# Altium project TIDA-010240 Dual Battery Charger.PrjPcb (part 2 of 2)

## Sheet BQ25731_A.SchDoc
size 431 x 279 mm; Date: Not shown in title block; ApprovedBy: Not shown in title block; CheckedBy: Not shown in title block; Author: Not shown in title block; CompanyName: Not shown in title block; Engineer: Not shown in title block; Organization: Not shown in title block; Address1: Not shown in title block; Address2: Not shown in title block; Address3: Not shown in title block; Address4: Not shown in title block; DocumentNumber: 5; Revision: Use project parameter SCH_Rev; SheetNumber: 5; SheetTotal: 6; PageSetup: Record=PageOptions¦CenterHorizontal=True¦CenterVertical=True¦PrintScale=1.00¦XCorrection=1.00¦YCorrection=1.00¦PrintKind=0¦BorderSize=5000000¦LeftOffset=0¦BottomOffset=0¦Orientation=2¦PaperLength=1000¦PaperWidth=1000¦Scale=100¦PaperSource=15¦PrintQuality=600¦MediaType=1¦DitherType=10¦PaperKind=Letter¦PrintScaleMode=1
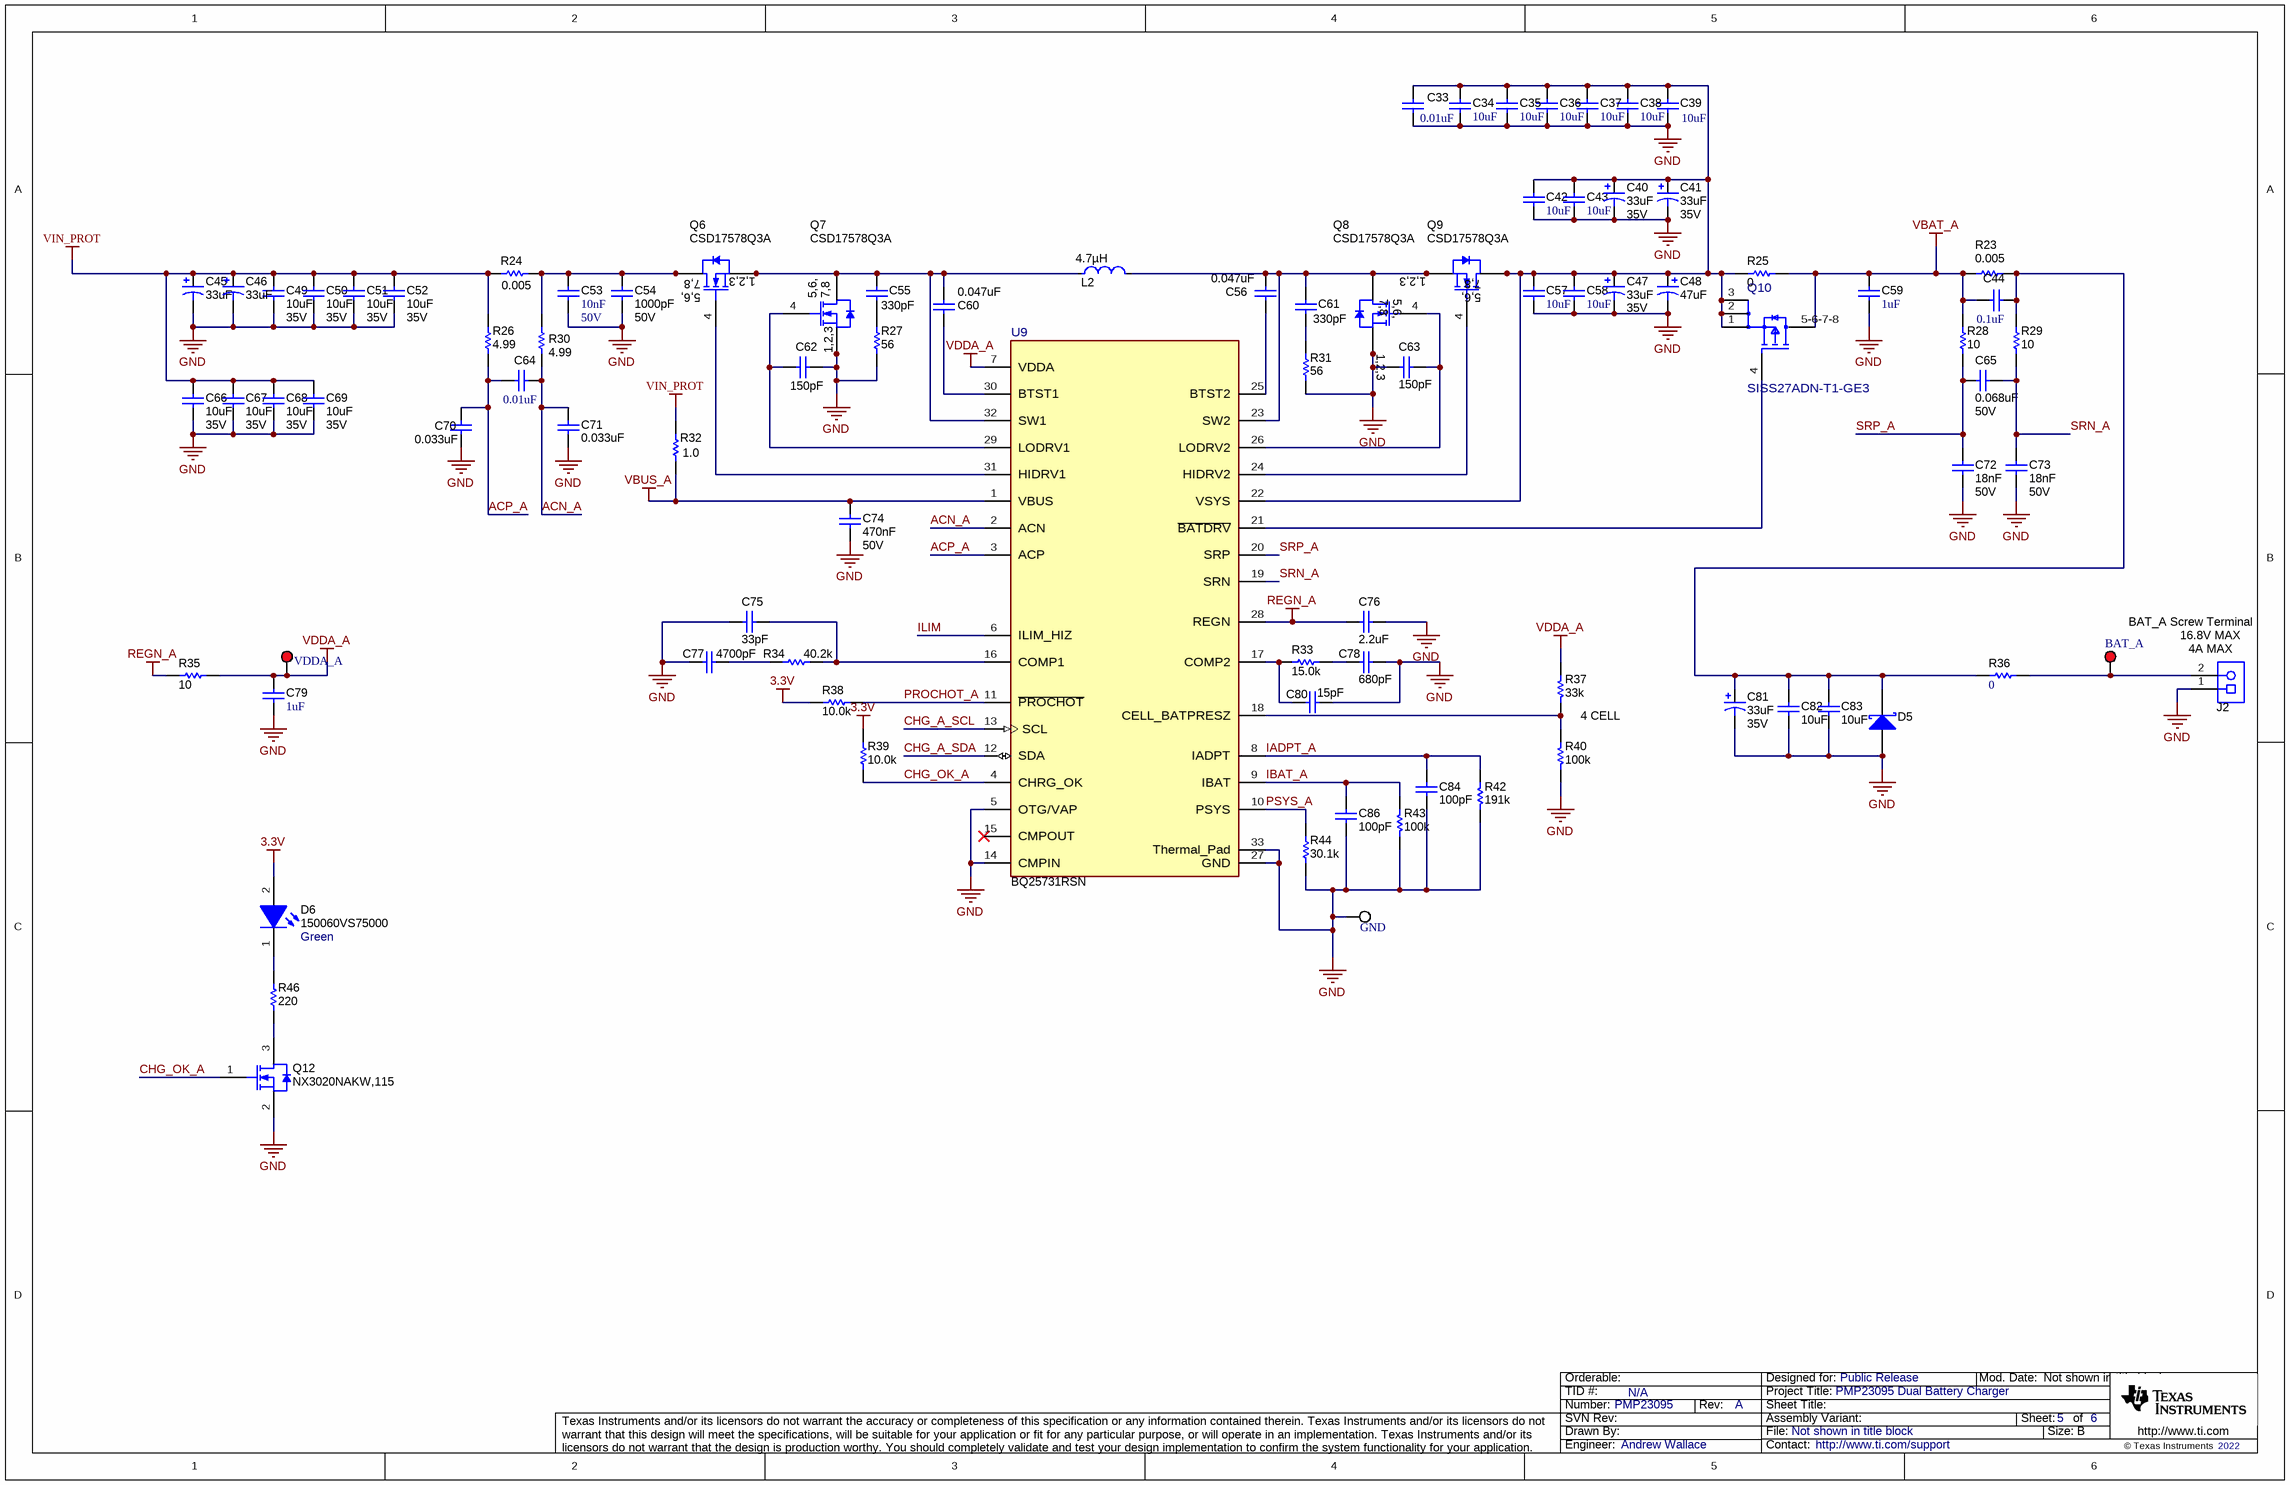
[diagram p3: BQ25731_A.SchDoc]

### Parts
BAT_A  5010  [Keystone5010]  (value not drawn)
C33  ValueDisplayed: 0.01uF  [0603L]  (hidden comment: C0603C103J5RACTU)
C34  ValueDisplayed: 10uF  [0805L]  (hidden comment: GRM21BR6YA106KE43L)
C35  ValueDisplayed: 10uF  [0805L]  (hidden comment: GRM21BR6YA106KE43L)
C36  ValueDisplayed: 10uF  [0805L]  (hidden comment: GRM21BR6YA106KE43L)
C37  ValueDisplayed: 10uF  [0805L]  (hidden comment: GRM21BR6YA106KE43L)
C38  ValueDisplayed: 10uF  [0805L]  (hidden comment: GRM21BR6YA106KE43L)
C39  ValueDisplayed: 10uF  [0805L]  (hidden comment: GRM21BR6YA106KE43L)
C40  ValueDisplayed: 33uF  VDC_V: 35V  [7343-31]  (hidden comment: T521D336M035ATE065)
C41  ValueDisplayed: 33uF  VDC_V: 35V  [7343-31]  (hidden comment: T521D336M035ATE065)
C42  ValueDisplayed: 10uF  [0805L]  (hidden comment: GRM21BR6YA106KE43L)
C43  ValueDisplayed: 10uF  [0805L]  (hidden comment: GRM21BR6YA106KE43L)
C44  ValueDisplayed: 0.1uF  [0603L]  (hidden comment: CGA3E2X7R1H104K080AA)
C45  ValueDisplayed: 33uF  [7343-31]  (hidden comment: T521D336M035ATE065)
C46  ValueDisplayed: 33uF  [7343-31]  (hidden comment: T521D336M035ATE065)
C47  ValueDisplayed: 33uF  VDC_V: 35V  [7343-31]  (hidden comment: T521D336M035ATE065)
C48  ValueDisplayed: 47uF  [CAPSMT_62_F61]  (hidden comment: Cap_Polarized)
C49  ValueDisplayed: 10uF  VDC_V: 35V  [0805L]  (hidden comment: GRM21BR6YA106KE43L)
C50  ValueDisplayed: 10uF  VDC_V: 35V  [0805L]  (hidden comment: GRM21BR6YA106KE43L)
C51  ValueDisplayed: 10uF  VDC_V: 35V  [0805L]  (hidden comment: GRM21BR6YA106KE43L)
C52  ValueDisplayed: 10uF  VDC_V: 35V  [0805L]  (hidden comment: GRM21BR6YA106KE43L)
C53  Cap_F: 10nF  VDC_V: 50V  [0603L]  (hidden comment: C0603C103J5RACTU)
C54  ValueDisplayed: 1000pF  VDC_V: 50V  [0402L]  (hidden comment: C1005NP01H102J050BA)
C55  ValueDisplayed: 330pF  [0603L]  (hidden comment: Capacitor)
C56  ValueDisplayed: 0.047uF  [0603L]  (hidden comment: Capacitor)
C57  ValueDisplayed: 10uF  [0805L]  (hidden comment: GRM21BR6YA106KE43L)
C58  ValueDisplayed: 10uF  [0805L]  (hidden comment: GRM21BR6YA106KE43L)
C59  ValueDisplayed: 1uF  [0603L]  (hidden comment: CGA3E1X7R1V105K080AC)
C60  ValueDisplayed: 0.047uF  [0603L]  (hidden comment: Capacitor)
C61  ValueDisplayed: 330pF  [0603L]  (hidden comment: Capacitor)
C62  ValueDisplayed: 150pF  [0603L]  (hidden comment: Capacitor)
C63  ValueDisplayed: 150pF  [0603L]  (hidden comment: Capacitor)
C64  ValueDisplayed: 0.01uF  [0603L]  (hidden comment: C0603C103J5RACTU)
C65  ValueDisplayed: 0.068uF  VDC_V: 50V  [0402L]  (hidden comment: CGA2B3X7R1H683K050BB)
C66  ValueDisplayed: 10uF  VDC_V: 35V  [0805L]  (hidden comment: GRM21BR6YA106KE43L)
C67  ValueDisplayed: 10uF  VDC_V: 35V  [0805L]  (hidden comment: GRM21BR6YA106KE43L)
C68  ValueDisplayed: 10uF  VDC_V: 35V  [0805L]  (hidden comment: GRM21BR6YA106KE43L)
C69  ValueDisplayed: 10uF  VDC_V: 35V  [0805L]  (hidden comment: GRM21BR6YA106KE43L)
C70  ValueDisplayed: 0.033uF  [0603L]  (hidden comment: GRM188R71H333KA61D)
C71  ValueDisplayed: 0.033uF  [0603L]  (hidden comment: GRM188R71H333KA61D)
C72  Cap_F: 18nF  VDC_V: 50V  [0603L]  (hidden comment: GRM188R71H183KA01D)
C73  Cap_F: 18nF  VDC_V: 50V  [0603L]  (hidden comment: GRM188R71H183KA01D)
C74  Cap_F: 470nF  VDC_V: 50V  [0805L]  (hidden comment: C2012X7R1H474K125AB)
C75  ValueDisplayed: 33pF  [0402L]  (hidden comment: Capacitor)
C76  ValueDisplayed: 2.2uF  [0603L]  (hidden comment: Capacitor)
C77  ValueDisplayed: 4700pF  [0402L]  (hidden comment: GRM155R71H472KA01D)
C78  ValueDisplayed: 680pF  [0402L]  (hidden comment: Capacitor)
C79  ValueDisplayed: 1uF  [0603L]  (hidden comment: CGA3E1X7R1V105K080AC)
C80  ValueDisplayed: 15pF  [0402L]  (hidden comment: Capacitor)
C81  ValueDisplayed: 33uF  VDC_V: 35V  [7343-31]  (hidden comment: T521D336M035ATE065)
C82  ValueDisplayed: 10uF  [1206_180]  (hidden comment: Capacitor)
C83  ValueDisplayed: 10uF  [1206_180]  (hidden comment: Capacitor)
C84  ValueDisplayed: 100pF  [0603L]  (hidden comment: Capacitor)
C86  ValueDisplayed: 100pF  [0603L]  (hidden comment: Capacitor)
D5  B220A-13-F  [SMA]  (value not drawn)
D6  150060VS75000  value Green  [WL-SMCW_GREEN]
GND  5015  [Testpoint_Keystone_Miniature]  (value not drawn)
J2  Receptacle_2x1  [On-Shore_ED120_2DS]  (value not drawn)
L2  Ind_H: 4.7µH  [FP-BMRHDY1010302R2MA1_SMT_IND_11MM2_10MM1-MFG]  (hidden comment: BMRHDY1010302R2MA1)
Q6  CSD17578Q3A  [DNH0008A]
Q7  CSD17578Q3A  [DNH0008A]
Q8  CSD17578Q3A  [DNH0008A]
Q9  CSD17578Q3A  [DNH0008A]
Q10  SISS27ADN-T1-GE3  [FP-SISS27ADN-T1-GE3_PowerPAK1212-8S-MFG]
Q12  NX3020NAKW,115  [SOT-323]
R23  ValueDisplayed: 0.005  [1206]  (hidden comment: WSLP12065L000FEA)
R24  ValueDisplayed: 0.005  [1206]  (hidden comment: WSLP12065L000FEA)
R25  ValueDisplayed: 0  [5106]  (hidden comment: 5106)
R26  ValueDisplayed: 4.99  [0603L]  (hidden comment: Resistor)
R27  ValueDisplayed: 56  [0603L]  (hidden comment: Resistor)
R28  ValueDisplayed: 10  [0603L]  (hidden comment: Resistor)
R29  ValueDisplayed: 10  [0603L]  (hidden comment: Resistor)
R30  ValueDisplayed: 4.99  [0603L]  (hidden comment: Resistor)
R31  ValueDisplayed: 56  [0603L]  (hidden comment: Resistor)
R32  ValueDisplayed: 1.0  [0805_HV]  (hidden comment: Resistor)
R33  ValueDisplayed: 15.0k  [0402L]  (hidden comment: CRCW040215K0FKED)
R34  ValueDisplayed: 40.2k  [0402L]  (hidden comment: Resistor)
R35  ValueDisplayed: 10  [0603L]  (hidden comment: CRCW060310R0JNEA)
R36  ValueDisplayed: 0  [2010]  (hidden comment: CRCW20100000Z0EF)
R37  ValueDisplayed: 33k  [0603L]  (hidden comment: CRCW060333K0JNEA)
R38  ValueDisplayed: 10.0k  [0603L]  (hidden comment: Resistor)
R39  ValueDisplayed: 10.0k  [0603L]  (hidden comment: Resistor)
R40  ValueDisplayed: 100k  [0603L]  (hidden comment: RC0603FR-07100KL)
R42  ValueDisplayed: 191k  [0603L]  (hidden comment: CRCW0603191KFKEA)
R43  ValueDisplayed: 100k  [0603L]  (hidden comment: CRCW0603100KFKEA)
R44  value 30.1k  [0603L]  (hidden comment: Resistor)
R46  ValueDisplayed: 220  [0603]  (hidden comment: RC0603FR-07220RL)
U9  BQ25731RSN  [RSN0032B-MFG]
VDDA_A  5010  [Keystone5010]  (value not drawn)

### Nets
3.3V: D6.2(A) R38.2 R39.2
GND: C33.2 C34.2 C35.2 C36.2 C37.2 C38.2 C39.2 C40.2(-) C41.2(-) C42.2 C43.2 C45.2(-) C46.2(-) C47.2(-) C48.2(-) C49.2 C50.2 C51.2 C52.2 C53.2 C54.2 C57.2 C58.2 C59.2 C62.2 C63.1 C66.2 C67.2 C68.2 C69.2 C70.2 C71.2 C72.2 C73.2 C74.2 C75.1 C76.2 C77.1 C78.2 C79.2 C80.2 C81.2(-) C82.2 C83.2 C84.2 C86.2 D5.2(A) GND.1 J2.1 Q7.1(S) Q7.2(S) Q7.3(S) Q8.1(S) Q8.2(S) Q8.3(S) Q12.2(S) R27.1 R31.1 R40.1 R42.1 R43.1 R44.2 U9.5(OTG/VAP) U9.14(CMPIN) U9.27(GND) U9.33(Thermal_Pad)
REGN_A: C76.1 R35.1 U9.28(REGN)
VBAT_A: C44.1 C59.1 Q10.5-6-7-8(D) R23.1 R25.2 R28.2
VBUS_A: C74.1 R32.1 U9.1(VBUS)
VDDA_A: C79.1 R35.2 R37.2 U9.7(VDDA) VDDA_A.1
VIN_PROT: C45.1(+) C46.1(+) C49.1 C50.1 C51.1 C52.1 C66.1 C67.1 C68.1 C69.1 R24.1 R26.2 R32.2  [project net IN_ISNS_N]
ACN_A: C64.2 C71.1 R30.1 U9.2(ACN)
ACP_A: C64.1 C70.1 R26.1 U9.3(ACP)
CHG_A_SCL: U9.13(SCL)
CHG_A_SDA: U9.12(SDA)
CHG_OK_A: Q12.1(G) R39.1 U9.4(CHRG_OK)
IADPT_A: C84.1 R42.2 U9.8(IADPT)
IBAT_A: C86.1 R43.2 U9.9(IBAT)
ILIM: U9.6(ILIM_HIZ)
PROCHOT_A: R38.1 U9.11(~{PROCHOT})
PSYS_A: R44.1 U9.10(PSYS)
SRN_A: C65.2 C73.1 R29.1 U9.19(SRN)
SRP_A: C65.1 C72.1 R28.1 U9.20(SRP)
NetBAT_A_1: BAT_A.1 J2.2 R36.2
NetC33_1: C33.1 C34.1 C35.1 C36.1 C37.1 C38.1 C39.1 C40.1(+) C41.1(+) C42.1 C43.1 C47.1(+) C48.1(+) C57.1 C58.1 Q9.5(D) Q9.6(D) Q9.7(D) Q9.8(D) Q9.9(D) Q10.1(S) Q10.2(S) Q10.3(S) R25.1 U9.22(VSYS)
NetC44_2: C44.2 C81.1(+) C82.1 C83.1 D5.1(K) R23.2 R29.2 R36.1
NetC53_1: C53.1 C54.1 Q6.5(D) Q6.6(D) Q6.7(D) Q6.8(D) Q6.9(D) R24.2 R30.2
NetC55_1: C55.1 C60.2 L2.1 Q6.1(S) Q6.2(S) Q6.3(S) Q7.5(D) Q7.6(D) Q7.7(D) Q7.8(D) Q7.9(D) U9.32(SW1)
NetC55_2: C55.2 R27.2
NetC56_1: C56.1 U9.25(BTST2)
NetC56_2: C56.2 C61.1 L2.2 Q8.5(D) Q8.6(D) Q8.7(D) Q8.8(D) Q8.9(D) Q9.1(S) Q9.2(S) Q9.3(S) U9.23(SW2)
NetC60_1: C60.1 U9.30(BTST1)
NetC61_2: C61.2 R31.2
NetC62_1: C62.1 Q7.4(G) U9.29(LODRV1)
NetC63_2: C63.2 Q8.4(G) U9.26(LODRV2)
NetC75_2: C75.2 R34.2 U9.16(COMP1)
NetC77_2: C77.2 R34.1
NetC78_1: C78.1 R33.2
NetC80_1: C80.1 R33.1 U9.17(COMP2)
NetD6_1: D6.1(K) R46.2
NetQ6_4: Q6.4(G) U9.31(HIDRV1)
NetQ9_4: Q9.4(G) U9.24(HIDRV2)
NetQ10_4: Q10.4(G) U9.21(~{BATDRV})
NetQ12_3: Q12.3(D) R46.1
NetR37_1: R37.1 R40.2 U9.18(CELL_BATPRESZ)

Not connected (* = marked no-connect by the designer): U9 15(CMPOUT)*

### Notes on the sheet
- BAT_A Screw Terminal
- (near J2) 16.8V MAX
- (near J2) 4A MAX
- 4 CELL

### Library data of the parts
BAT_A VDDA_A = CMP-0055147-1: Test Point, Multipurpose, Red, TH; Manufacturer: Keystone; CNHeader: FALSE; Green_Lifecycle: Active; Green_REACh: Passed; CT: TRUE; ContactFinish: Silver
C33 = CMP-0006850-4: CAP, CERM, 0.01 uF, 50 V, +/- 5%, X7R, 0603; Manufacturer: Kemet; Polarized: N; Value: 0.01uF; U/M: EA; Cap_F: 10nF; Value1: Unknown; VDC_V: 50V; TaMin_C: -55°C; TaMax_C: 125°C; Cap_Case: 0603; SizeAreaWB_mm2: 4.68; SizeZ_mm: 1; SizeX_mm: 1.6; SizeY_mm: 0.8; SizeArea_mm2: 1.28; AEC Category: Q200
C34-C39 C42 C43 C57 C58 = CMP-0008310-2: CAP, CERM, 10 uF, 35 V, +/- 10%, X5R, 0805; Manufacturer: MuRata; Polarized: N; Value: 10uF; U/M: EA; Cap_F: 10µF; Value1: Unknown; VDC_V: 35V; TaMin_C: -55°C; TaMax_C: 85°C; Cap_Case: 0805; SizeArea_mm2: 2.5; SizeAreaWB_mm2: 6.75; SizeX_mm: 2; SizeY_mm: 1.25; SizeZ_mm: 1.45; AEC Category: Q200
C40 C41 C47 C81 = CMP-0011849-2: CAP, TA, 33 uF, 35 V, +/- 20%, 0.065 ohm, SMD; Manufacturer: Kemet; Polarized: Y; CompType: Capacitor; Value: 33uF; U/M: EA; Cap_F: 33µF; ESR_ohm: 0.065; IRMS_A: 1.9A; TaMin_C: -55°C; TaMax_C: 125°C; AEC Category: Q200; AEC Qualified: N; SizeAreaWB_mm2: 58.59; SizeArea_mm2: 31.39; SizeX_mm: 7.3; SizeY_mm: 4.3; SizeZ_mm: 3.1
C44 = CMP-0007078-4: CAP, CERM, 0.1 uF, 50 V, +/- 10%, X7R, AEC-Q200 Grade 1, 0603; Manufacturer: TDK; Polarized: N; Value: 0.1uF; U/M: EA; Cap_F: 100nF; ESR_ohm: 29.6m; Value1: 0.0296 ohm; VDC_V: 50V; IRMS_A: 971.99mA; TaMin_C: -55°C; TaMax_C: 125°C; Cap_Case: 0603; SizeAreaWB_mm2: 4.68; SizeZ_mm: 1; SizeX_mm: 1.6; SizeY_mm: 0.8; SizeArea_mm2: 1.28; AEC Qualified: Y; AEC Category: Q200
C45 C46 = CMP-0011849-2: CAP, TA, 33 uF, 35 V, +/- 20%, 0.065 ohm, SMD; Manufacturer: Kemet; Polarized: Y; CompType: Capacitor; Value: 33uF; U/M: EA; Cap_F: 33µF; VDC_V: 35V; ESR_ohm: 0.065; IRMS_A: 1.9A; TaMin_C: -55°C; TaMax_C: 125°C; AEC Category: Q200; AEC Qualified: N; SizeAreaWB_mm2: 58.59; SizeArea_mm2: 31.39; SizeX_mm: 7.3; SizeY_mm: 4.3; SizeZ_mm: 3.1
C48 = CMP-0012121-3: CAP, Aluminum Polymer, 47 uF, 25 V, +/- 20%, 0.03 ohm, F61 SMD; PartNumber: 25SVPF47M; Manufacturer: Panasonic; Polarized: Y; CompType: Capacitor; Value: 47uF; U/M: EA; Cap_F: 47µF; VDC_V: 25V; ESR_ohm: 0.03; IRMS_A: 2.8A; TaMin_C: -55°C; TaMax_C: 105°C; AEC Category: Q200; SizeAreaWB_mm2: 73.96; SizeZ_mm: 5.8; SizeX_mm: 6.6; SizeArea_mm2: 43.56
C49-C52 C66-C69 = CMP-0008310-2: CAP, CERM, 10 uF, 35 V, +/- 10%, X5R, 0805; Manufacturer: MuRata; Polarized: N; Value: 10uF; U/M: EA; Cap_F: 10µF; Value1: Unknown; TaMin_C: -55°C; TaMax_C: 85°C; Cap_Case: 0805; SizeArea_mm2: 2.5; SizeAreaWB_mm2: 6.75; SizeX_mm: 2; SizeY_mm: 1.25; SizeZ_mm: 1.45; AEC Category: Q200
C53 = CMP-0006850-4: CAP, CERM, 0.01 uF, 50 V, +/- 5%, X7R, 0603; Manufacturer: Kemet; Polarized: N; Value: 0.01uF; U/M: EA; Value1: Unknown; TaMin_C: -55°C; TaMax_C: 125°C; Cap_Case: 0603; AEC Category: Q200; SizeAreaWB_mm2: 4.68; SizeZ_mm: 1; SizeX_mm: 1.6; SizeY_mm: 0.8; SizeArea_mm2: 1.28
C54 = CMP-0006254-2: CAP, CERM, 1000 pF, 50 V, +/- 5%, C0G/NP0, 0402; Manufacturer: TDK; Polarized: N; Value: 1000pF; U/M: EA; Cap_F: 1nF; Value1: Unknown; TaMin_C: -55°C; TaMax_C: 150°C; Cap_Case: 0402; SizeAreaWB_mm2: 3; SizeZ_mm: 0.6; SizeX_mm: 1; SizeY_mm: 0.5; AEC Category: Q200
C55 C61 = CMP-0007449-4: CAP, CERM, 330 pF, 50 V, +/- 10%, X7R, 0603; PartNumber: GRM188R71H331KA01D; Manufacturer: MuRata; Polarized: N; Value: 330pF; U/M: EA; Value1: Unknown; VDC_V: 50V; TaMin_C: -55°C; TaMax_C: 125°C; Cap_Case: 0603; SizeAreaWB_mm2: 4.68; SizeZ_mm: 1; SizeX_mm: 1.6; SizeY_mm: 0.8; SizeArea_mm2: 1.28; AEC Category: Q200
C56 C60 = CMP-0007423-4: CAP, CERM, 0.047 uF, 25 V, +/- 10%, X7R, 0603; PartNumber: GRM188R71E473KA01D; Manufacturer: MuRata; Polarized: N; U/M: EA; Cap_F: 47nF; Value1: Unknown; VDC_V: 25V; TaMin_C: -55°C; TaMax_C: 125°C; Cap_Case: 0603; SizeAreaWB_mm2: 4.68; SizeZ_mm: 1; SizeX_mm: 1.6; SizeY_mm: 0.8; SizeArea_mm2: 1.28; AEC Category: Q200
C59 C79 = CMP-0007067-4: CAP, CERM, 1 uF, 35 V, +/- 10%, X7R, AEC-Q200 Grade 1, 0603; Manufacturer: TDK; Polarized: N; Value: 1uF; U/M: EA; Cap_F: 1µF; ESR_ohm: 5.522m; Value1: 0.005522 ohm; VDC_V: 35V; IRMS_A: 2.2162A; TaMin_C: -55°C; TaMax_C: 125°C; Cap_Case: 0603; SizeAreaWB_mm2: 4.68; SizeZ_mm: 1; SizeX_mm: 1.6; SizeY_mm: 0.8; SizeArea_mm2: 1.28; AEC Qualified: Y; AEC Category: Q200
C62 C63 = CMP-0006880-4: CAP, CERM, 150 pF, 50 V, +/- 5%, C0G/NP0, 0603; PartNumber: C0603C151J5GACTU; Manufacturer: Kemet; Polarized: N; Value: 150pF; U/M: EA; Value1: Unknown; VDC_V: 50V; TaMin_C: -55°C; TaMax_C: 125°C; Cap_Case: 0603; AEC Category: Q200; SizeAreaWB_mm2: 4.68; SizeZ_mm: 1; SizeX_mm: 1.6; SizeY_mm: 0.8; SizeArea_mm2: 1.28
C64 = CMP-0006850-4: CAP, CERM, 0.01 uF, 50 V, +/- 5%, X7R, 0603; Manufacturer: Kemet; Polarized: N; Value: 0.01uF; U/M: EA; Cap_F: 10nF; Value1: Unknown; VDC_V: 50V; TaMin_C: -55°C; TaMax_C: 125°C; Cap_Case: 0603; AEC Category: Q200; SizeAreaWB_mm2: 4.68; SizeZ_mm: 1; SizeX_mm: 1.6; SizeY_mm: 0.8; SizeArea_mm2: 1.28
C65 = CMP-0006331-2: CAP, CERM, 0.068 uF, 50 V, +/- 10%, X7R, AEC-Q200 Grade 1, 0402; Manufacturer: TDK; Polarized: N; U/M: EA; Cap_F: 68nF; ESR_ohm: 0.05606; Value1: 0.05606 ohm; IRMS_A: 684.724mA; TaMin_C: -55°C; TaMax_C: 125°C; Cap_Case: 0402; SizeAreaWB_mm2: 3; SizeZ_mm: 0.6; SizeX_mm: 1; SizeY_mm: 0.5; AEC Qualified: Y; AEC Category: Q200
C70 C71 = CMP-0007451-4: CAP, CERM, 0.033 uF, 50 V, +/- 10%, X7R, 0603; Manufacturer: MuRata; Polarized: N; U/M: EA; Cap_F: 33nF; Value1: Unknown; VDC_V: 50V; TaMin_C: -55°C; TaMax_C: 125°C; Cap_Case: 0603; AEC Category: Q200; SizeArea_mm2: 1.28; SizeAreaWB_mm2: 4.68; SizeX_mm: 1.6; SizeY_mm: 0.8; SizeZ_mm: 1
C72 C73 = CMP-0007440-5: CAP, CERM, 0.018 uF, 50 V, +/- 10%, X7R, 0603; Manufacturer: MuRata; Polarized: N; U/M: EA; Value1: Unknown; TaMin_C: -55°C; TaMax_C: 125°C; Cap_Case: 0603; AEC Category: Q200; SizeArea_mm2: 1.28; SizeAreaWB_mm2: 4.68; SizeX_mm: 1.6; SizeY_mm: 0.8; SizeZ_mm: 1
C74 = CMP-0007880-2: CAP, CERM, 0.47 uF, 50 V, +/- 10%, X7R, 0805; Manufacturer: TDK; Polarized: N; Value: 0.47uF; U/M: EA; ESR_ohm: 0.022012; Value1: 0.022012 ohm; IRMS_A: 1.39566A; TaMin_C: -55°C; TaMax_C: 125°C; Cap_Case: 0805; AEC Category: Q200; SizeAreaWB_mm2: 6.75; SizeZ_mm: 1.45; SizeX_mm: 2; SizeY_mm: 1.25; SizeArea_mm2: 2.5
C75 = CMP-0006454-2: CAP, CERM, 33 pF, 50 V, +/- 5%, C0G/NP0, 0402; PartNumber: GRM1555C1H330JA01D; Manufacturer: MuRata; Polarized: N; Value: 33pF; U/M: EA; Value1: Unknown; VDC_V: 50V; TaMin_C: -55°C; TaMax_C: 125°C; Cap_Case: 0402; AEC Category: Q200; SizeArea_mm2: 0.5; SizeAreaWB_mm2: 3; SizeX_mm: 1; SizeZ_mm: 0.6
C76 = CMP-0007356-5: CAP, CERM, 2.2 uF, 35 V, +/- 10%, X5R, 0603; PartNumber: GRM188R6YA225KA12D; Manufacturer: MuRata; Polarized: N; Value: 2.2uF; U/M: EA; Cap_F: 2.2µF; Value1: Unknown; VDC_V: 35V; TaMin_C: -55°C; TaMax_C: 85°C; Cap_Case: 0603; SizeAreaWB_mm2: 4.68; SizeZ_mm: 1; SizeX_mm: 1.6; SizeY_mm: 0.8; SizeArea_mm2: 1.28; AEC Category: Q200
C77 = CMP-0006692-2: CAP, CERM, 4700 pF, 50 V, +/- 10%, X7R, 0402; Manufacturer: MuRata; Polarized: N; Value: 4700pF; U/M: EA; Cap_F: 4.7nF; Value1: Unknown; VDC_V: 50V; TaMin_C: -55°C; TaMax_C: 125°C; Cap_Case: 0402; AEC Category: Q200; SizeAreaWB_mm2: 3; SizeZ_mm: 0.6; SizeX_mm: 1; SizeY_mm: 0.5
C78 = CMP-0006486-2: CAP, CERM, 680 pF, 50 V, +/- 5%, C0G/NP0, 0402; PartNumber: GRM1555C1H681JA01D; Manufacturer: MuRata; Polarized: N; Value: 680pF; U/M: EA; Value1: Unknown; VDC_V: 50V; TaMin_C: -55°C; TaMax_C: 125°C; Cap_Case: 0402; AEC Category: Q200; SizeAreaWB_mm2: 3; SizeZ_mm: 0.6; SizeX_mm: 1; SizeY_mm: 0.5
C80 = CMP-0006420-2: CAP, CERM, 15 pF, 50 V, +/- 5%, C0G/NP0, 0402; PartNumber: GRM1555C1H150JA01D; Manufacturer: MuRata; Polarized: N; Value: 15pF; U/M: EA; Value1: Unknown; VDC_V: 50V; TaMin_C: -55°C; TaMax_C: 125°C; Cap_Case: 0402; AEC Category: Q200; SizeAreaWB_mm2: 3; SizeZ_mm: 0.6; SizeX_mm: 1; SizeY_mm: 0.5
C82 C83 = CMP-0008965-2: CAP, CERM, 10 uF, 25 V, +/- 10%, X7R, 1206; PartNumber: GRM31CR71E106KA12L; Manufacturer: MuRata; Polarized: N; Value: 10uF; U/M: EA; Cap_F: 10µF; Value1: Unknown; VDC_V: 25V; TaMin_C: -55°C; TaMax_C: 125°C; Cap_Case: 2220; SizeArea_mm2: 5.12; SizeAreaWB_mm2: 10.92; SizeX_mm: 3.2; SizeY_mm: 1.6; SizeZ_mm: 1.8; AEC Category: Q200
C84 C86 = CMP-0006840-4: CAP, CERM, 100 pF, 50 V, +/- 5%, C0G/NP0, 0603; PartNumber: C0603C101J5GAC; Manufacturer: Kemet; Polarized: N; Value: 100pF; U/M: EA; Value1: Unknown; VDC_V: 50V; TaMin_C: -55°C; TaMax_C: 125°C; Cap_Case: 0603; SizeAreaWB_mm2: 4.68; SizeZ_mm: 1; SizeX_mm: 1.6; SizeY_mm: 0.8; SizeArea_mm2: 1.28; AEC Category: Q200
D5 = CMP-0028399-2: Diode, Schottky, 20 V, 2 A, SMA; Manufacturer: Diodes Inc.; Vf_V: 500mV; Value: 20V; Value1: 2A; Value2: 0.5V; TJmax_C: 150°C; RJC_CperW: 20; Green_REACh: Passed; SizeAreaWB_mm2: 37.3428; SizeZ_mm: 2.87; SizeX_mm: 5.59; SizeArea_mm2: 16.3228; SizeY_mm: 2.92; Green_Lifecycle: Active; AEC Category: Q101
D6 = CMP-0002894-2: LED, Green, SMD; Manufacturer: Wurth Elektronik; Type: AlInGaP; Value2: 2V; Io_A: 20mA; Value1: W
GND = CMP-0055152-1: Test Point, Miniature, SMT; Manufacturer: Keystone; CNHeader: FALSE; Green_Lifecycle: Active; Green_REACh: Passed; CT: TRUE
J2 = CMP-0074910-1: Terminal Block, 5.08 mm, 2x1, Brass, TH; PartNumber: ED120/2DS; Manufacturer: On-Shore Technology; U/M: EA; Cert_VDE: Y; CNHeader: False; Current_A: 15A; Green_Lifecycle: Not Set; Shrouded: N; Gender: Female; Green_REACh: Incomplete; Voltage_V: 300V; Row_Count: 1; Pitch_mm: 5.08; CT: True
L2 = CMP-0088941-1: 2.2µH Shielded Wirewound Inductor 13A 9mOhm Max 10x10x3mm; Manufacturer: Chilisin Electronics; Isat: 16A; DCR_ohm: 9m; Material: Magnetic Metal Powder; AEC Qualified: No; SizeZ_mm: 3mm; Tolerance_%: 20%; Test Frequency: 100kHz
Q6-Q9 = CMP-0000591-2: MOSFET, N-CH, 30 V, 14 A, DNH0008A (VSONP-8); Alternate Manufacturer: None; Manufacturer: Texas Instruments; SizeZ_mm: 0.9; ChType: N; Value2: 7.9 nC; Value1: 0.008; VdsMax_V: 30V; SizeX_mm: 3.3; Vgs_V: 20V; Value: 30V; Rdson45_ohm: 8.2m; SizeArea_mm2: 10.89; AEC Category: Q101; IdsMax_A: 14A; SizeAreaWB_mm2: 18.49; QgTyp_nC: 7.9; ChMode: Enhancement
Q10 = CMP-0092727-1: P-Channel 30 V 5.1 mOhm 57 W TrenchFET Gen III Mosfet - PowerPAK 1212-8S; Manufacturer: Vishay; Typ Forward Diode Voltage: -0.8V; QgTyp_nC: 77.5nC @ -10V; TJmax_C: +150°C; Number Of P Channels: 1; Vgs_V: 20V; Threshold Vgs Min: -1V; Reverse Recovery Time: 40ns; ChMode: False; AEC Qualified: No; Rthja Max: 21°C/W; SizeZ_mm: 0.83mm; Pulse Drain Current: -200A; Turn On Delay Time: 12ns; Input Capacitace At Vds: 4660pF @ -15V; Power_W: 4.8W; VdsMax_V: -1.2V; Threshold Vgs Max: -2.2V; Turn Off Delay Time: 60ns; Transconductance: 57S; Rdson45_ohm: 4.2m; Standoff Height: 0mm; Reverse Recovery Charge: 22nC; Drain To Source Breakdown Voltage: -30V; IdsMax_A: -24.3A
Q12 = CMP-0000643-2: MOSFET, N-CH, 30 V, 0.18 A, SOT-323; Alternate Manufacturer: None; Manufacturer: Nexperia; SizeZ_mm: 1.1; ChType: N; Value2: 0.34 nC; Value1: 5; VdsMax_V: 30V; SizeX_mm: 2.2; Vgs_V: 20V; Value: 30V; Rdson45_ohm: 5.2; SizeArea_mm2: 4.84; AEC Category: Q101; IdsMax_A: 180mA; SizeAreaWB_mm2: 10.24; QgTyp_nC: 0.34
R23 R24 = CMP-0084411-1: RES, 0.005, 1%, 1 W, AEC-Q200 Grade 0, 1206; Manufacturer: Vishay-Dale; Value: 0.005; Res_ohm: 5m; Value_Code: 5L000; Power_W: 1W; TempCo: 110 ppm/C; EIA_Code: E96; SizeX_mm: 3.2; SizeY_mm: 1.6; SizeZ_mm: 1.35; SizeArea_mm2: 5.12; AEC Qualified: Y; AEC Category: Q200; AEC Grade: 0; Green_REACh: Passed; Green_Lifecycle: Active; SizeAreaWB_mm2: 10.92
R25 = CMP-0020833-2: RES, 0, 1%, 0.5 W, 0805; Manufacturer: Keystone; Power_W: 500mW; TempCo: ppm/C; U/M: EA; Value: 0; SizeX_mm: 2; SizeY_mm: 1.25; SizeZ_mm: 0.84; Value2: 0.5W; SizeArea_mm2: 2.5; AEC Qualified: N; AEC Category: Q200
R26 R30 = CMP-0022478-4: RES, 4.99, 1%, 0.1 W, AEC-Q200 Grade 0, 0603; PartNumber: CRCW06034R99FKEA; Manufacturer: Vishay-Dale; Value: 4.99; Value_Code: 4R99; Power_W: 100mW; Value2: 0.1W; VDC_V: 75V; TempCo: 100 ppm/C; EIA_Code: E96; U/M: EA; AEC Category: Q200; AEC Qualified: Y; AEC Grade: 0; SizeArea_mm2: 1.28; SizeX_mm: 1.6; SizeY_mm: 0.8; SizeZ_mm: 1
R27 R31 = CMP-0025829-4: RES, 56, 5%, 0.1 W, AEC-Q200 Grade 0, 0603; PartNumber: CRCW060356R0JNEA; Manufacturer: Vishay-Dale; Value: 56; Value_Code: 56R0; Power_W: 100mW; Value2: 0.1W; VDC_V: 75V; TempCo: 200 ppm/C; EIA_Code: E24; U/M: EA; SizeX_mm: 1.6; SizeY_mm: 0.8; SizeZ_mm: 1; SizeArea_mm2: 1.28; AEC Qualified: Y; AEC Category: Q200; AEC Grade: 0
R28 R29 = CMP-0025703-4: RES, 10, 5%, 0.1 W, AEC-Q200 Grade 0, 0603; PartNumber: CRCW060310R0JNEA; Manufacturer: Vishay-Dale; Value: 10; Value_Code: 10R0; Power_W: 100mW; Value2: 0.1W; VDC_V: 75V; TempCo: 200 ppm/C; EIA_Code: E24; U/M: EA; SizeX_mm: 1.6; SizeY_mm: 0.8; SizeZ_mm: 1; SizeArea_mm2: 1.28; AEC Qualified: Y; AEC Category: Q200; AEC Grade: 0
R32 = CMP-0020487-3: RES, 1.0, 5%, 0.125 W, AEC-Q200 Grade 0, 0805; PartNumber: CRCW08051R00JNEA; Manufacturer: Vishay-Dale; Value: 1.0; Res_ohm: 1; Value_Code: 1R00; Power_W: 125mW; Value2: 0.125W; VDC_V: 150V; TempCo: 200 ppm/C; EIA_Code: E24; U/M: EA; AEC Category: Q200; AEC Qualified: Y; AEC Grade: 0; SizeX_mm: 2; SizeY_mm: 1.25; SizeZ_mm: 1.45; SizeArea_mm2: 2.5
R33 = CMP-0026027-3: RES, 15.0 k, 1%, 0.063 W, AEC-Q200 Grade 0, 0402; Manufacturer: Vishay-Dale; Value: 15.0k; Res_ohm: 15k; Value_Code: 15k0; Power_W: 63mW; Value2: 0.063W; VDC_V: 50V; TempCo: 100 ppm/C; EIA_Code: E96; AEC Category: Q200; AEC Qualified: Y; AEC Grade: 0; SizeArea_mm2: 0.5; SizeX_mm: 1; SizeZ_mm: 0.6
R34 = CMP-0026367-2: RES, 40.2 k, 1%, 0.063 W, AEC-Q200 Grade 0, 0402; PartNumber: CRCW040240K2FKED; Manufacturer: Vishay-Dale; Value: 40.2k; Value_Code: 40k2; Power_W: 63mW; Value2: 0.063W; VDC_V: 50V; TempCo: 100 ppm/C; EIA_Code: E96; U/M: EA; AEC Category: Q200; AEC Qualified: Y; AEC Grade: 0; SizeX_mm: 1; SizeY_mm: 0.5; SizeZ_mm: 0.6
R35 = CMP-0025703-4: RES, 10, 5%, 0.1 W, AEC-Q200 Grade 0, 0603; Manufacturer: Vishay-Dale; Value: 10; Value_Code: 10R0; Power_W: 100mW; Value2: 0.1W; VDC_V: 75V; TempCo: 200 ppm/C; EIA_Code: E24; SizeX_mm: 1.6; SizeY_mm: 0.8; SizeZ_mm: 1; SizeArea_mm2: 1.28; AEC Qualified: Y; AEC Category: Q200; AEC Grade: 0
R36 = CMP-0016044-3: RES, 0, 5%, 0.75 W, AEC-Q200 Grade 0, 2010; Manufacturer: Vishay-Dale; Power_W: 750mW; TempCo: ppm/C; Value_Code: 0000; Value: 0; SizeX_mm: 5; SizeY_mm: 2.5; SizeZ_mm: 1.66; Value2: 0.75W; SizeArea_mm2: 12.5; AEC Qualified: Y; AEC Category: Q200; EIA_Code: E24
R37 = CMP-0025786-4: RES, 33 k, 5%, 0.1 W, AEC-Q200 Grade 0, 0603; Manufacturer: Vishay-Dale; Value: 33k; Value_Code: 33k0; Power_W: 100mW; Value2: 0.1W; VDC_V: 75V; TempCo: 200 ppm/C; EIA_Code: E24; SizeX_mm: 1.6; SizeY_mm: 0.8; SizeZ_mm: 1; SizeArea_mm2: 1.28; AEC Qualified: Y; AEC Category: Q200; AEC Grade: 0
R38 R39 = CMP-0021998-4: RES, 10.0 k, 1%, 0.1 W, AEC-Q200 Grade 0, 0603; PartNumber: CRCW060310K0FKEA; Manufacturer: Vishay-Dale; Value: 10.0k; Res_ohm: 10k; Value_Code: 10k0; Power_W: 100mW; Value2: 0.1W; VDC_V: 75V; TempCo: 100 ppm/C; EIA_Code: E96; U/M: EA; SizeX_mm: 1.6; SizeY_mm: 0.8; SizeZ_mm: 1; SizeArea_mm2: 1.28; AEC Qualified: Y; AEC Category: Q200; AEC Grade: 0
R40 = CMP-0022735-5: RES, 100 k, 1%, 0.1 W, 0603; Manufacturer: Yageo; Value: 100k; Power_W: 100mW; Value2: 0.1W; VDC_V: 75V; TempCo: 100 ppm/C; EIA_Code: E96; SizeX_mm: 1.6; SizeY_mm: 0.8; SizeZ_mm: 1; SizeArea_mm2: 1.28; AEC Qualified: N; AEC Category: Q200; SizeAreaWB_mm2: 4.68
R42 = CMP-0022101-4: RES, 191 k, 1%, 0.1 W, AEC-Q200 Grade 0, 0603; Manufacturer: Vishay-Dale; Value: 191k; Power_W: 100mW; Value2: 0.1W; VDC_V: 75V; TempCo: 100 ppm/C; EIA_Code: E96; AEC Category: Q200; AEC Qualified: Y; AEC Grade: 0; SizeArea_mm2: 1.28; SizeX_mm: 1.6; SizeY_mm: 0.8; SizeZ_mm: 1
R43 = CMP-0021990-4: RES, 100 k, 1%, 0.1 W, AEC-Q200 Grade 0, 0603; Manufacturer: Vishay-Dale; Value: 100k; Power_W: 100mW; Value2: 0.1W; VDC_V: 75V; TempCo: 100 ppm/C; EIA_Code: E96; AEC Category: Q200; AEC Qualified: Y; AEC Grade: 0; SizeArea_mm2: 1.28; SizeX_mm: 1.6; SizeY_mm: 0.8; SizeZ_mm: 1
R44 = CMP-0022324-4: RES, 30.1 k, 1%, 0.1 W, AEC-Q200 Grade 0, 0603; PartNumber: CRCW060330K1FKEA; Manufacturer: Vishay-Dale; Value_Code: 30k1; Power_W: 100mW; Value2: 0.1W; VDC_V: 75V; TempCo: 100 ppm/C; EIA_Code: E96; U/M: EA; SizeX_mm: 1.6; SizeY_mm: 0.8; SizeZ_mm: 1; SizeArea_mm2: 1.28; AEC Qualified: Y; AEC Category: Q200; AEC Grade: 0
R46 = CMP-0022918-5: RES, 220, 1%, 0.1 W, 0603; Manufacturer: Yageo; Power_W: 100mW; TempCo: 100 ppm/C; Value_Code: 220R; Value: 220; SizeX_mm: 1.6; SizeY_mm: 0.8; SizeZ_mm: 1; Value2: 0.1W; SizeArea_mm2: 1.28; AEC Qualified: N; VDC_V: 75V; AEC Category: Q200; SizeAreaWB_mm2: 4.68
U9 = CMP-0089013-3: No Description; Manufacturer: Texas Instruments; SizeZ_mm: 0.8mm; CompType: IC; AEC Category: Q200

## Sheet BQ25731_B.SchDoc
size 431 x 279 mm; Date: Not shown in title block; ApprovedBy: Not shown in title block; CheckedBy: Not shown in title block; Author: Not shown in title block; CompanyName: Not shown in title block; Engineer: Not shown in title block; Organization: Not shown in title block; Address1: Not shown in title block; Address2: Not shown in title block; Address3: Not shown in title block; Address4: Not shown in title block; DocumentNumber: 6; Revision: Use project parameter SCH_Rev; SheetNumber: 6; SheetTotal: 6; PageSetup: Record=PageOptions¦CenterHorizontal=True¦CenterVertical=True¦PrintScale=1.00¦XCorrection=1.00¦YCorrection=1.00¦PrintKind=0¦BorderSize=5000000¦LeftOffset=0¦BottomOffset=0¦Orientation=2¦PaperLength=1000¦PaperWidth=1000¦Scale=100¦PaperSource=15¦PrintQuality=600¦MediaType=1¦DitherType=10¦PaperKind=Letter¦PrintScaleMode=1
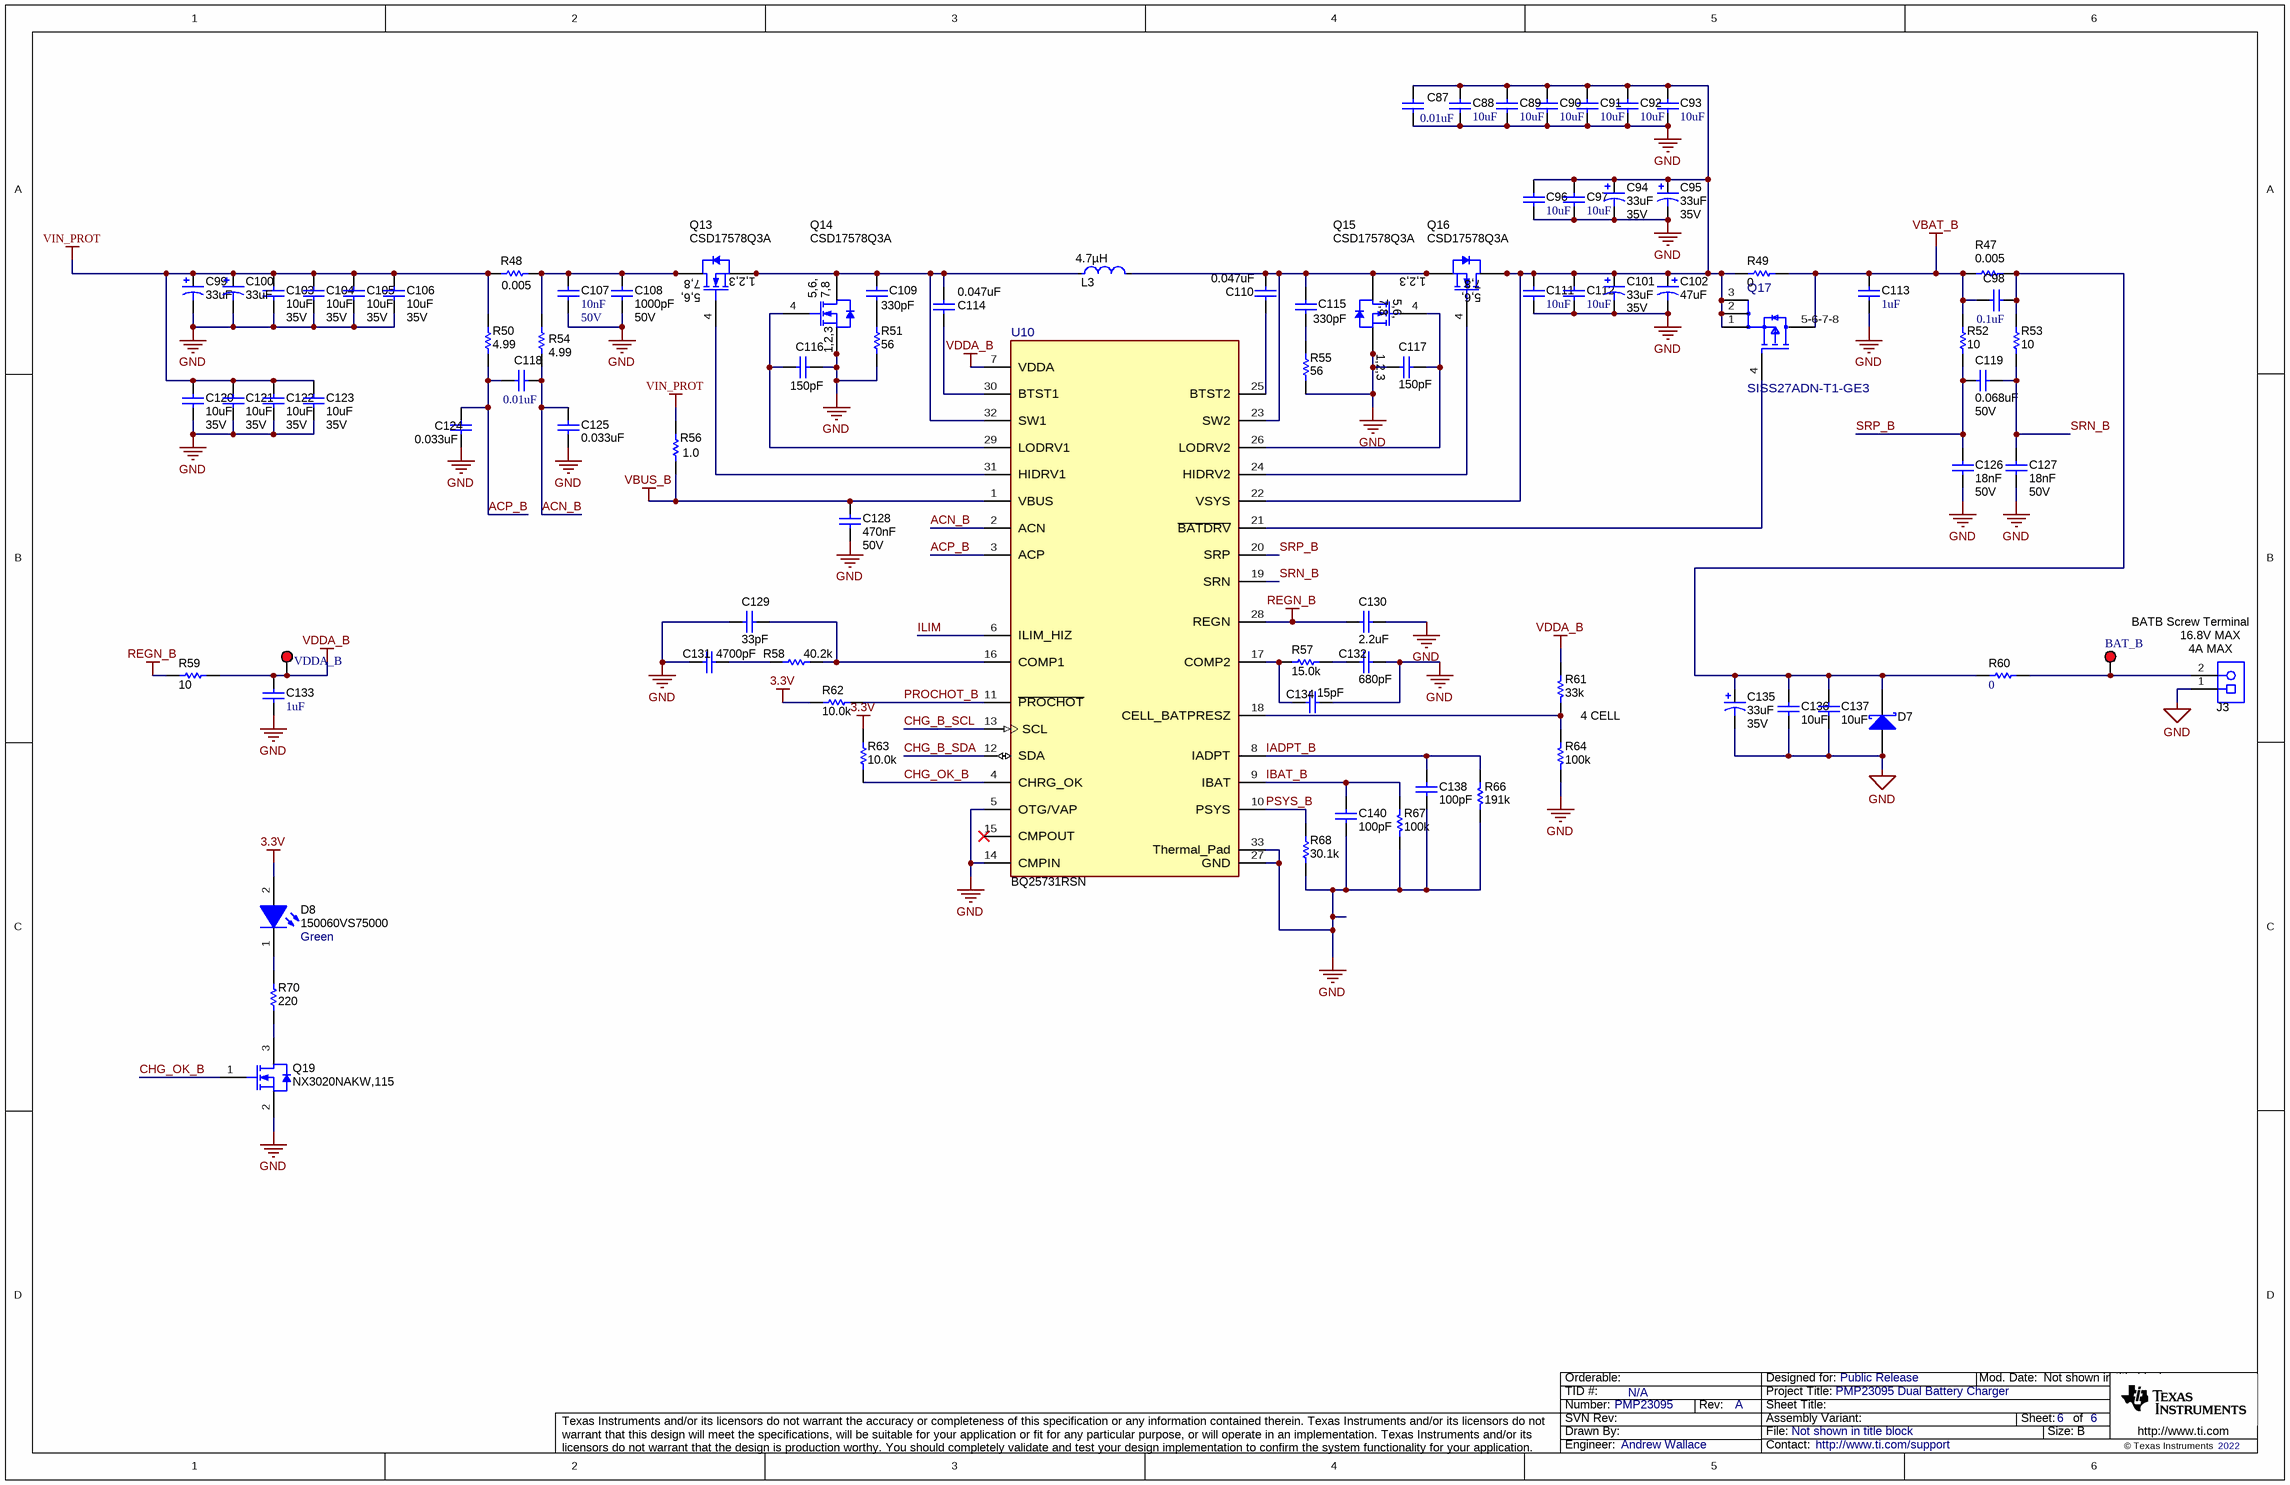
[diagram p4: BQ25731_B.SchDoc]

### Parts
BAT_B  5010  [Keystone5010]  (value not drawn)
C87  ValueDisplayed: 0.01uF  [0603L]  (hidden comment: C0603C103J5RACTU)
C88  ValueDisplayed: 10uF  [0805L]  (hidden comment: GRM21BR6YA106KE43L)
C89  ValueDisplayed: 10uF  [0805L]  (hidden comment: GRM21BR6YA106KE43L)
C90  ValueDisplayed: 10uF  [0805L]  (hidden comment: GRM21BR6YA106KE43L)
C91  ValueDisplayed: 10uF  [0805L]  (hidden comment: GRM21BR6YA106KE43L)
C92  ValueDisplayed: 10uF  [0805L]  (hidden comment: GRM21BR6YA106KE43L)
C93  ValueDisplayed: 10uF  [0805L]  (hidden comment: GRM21BR6YA106KE43L)
C94  ValueDisplayed: 33uF  VDC_V: 35V  [7343-31]  (hidden comment: T521D336M035ATE065)
C95  ValueDisplayed: 33uF  VDC_V: 35V  [7343-31]  (hidden comment: T521D336M035ATE065)
C96  ValueDisplayed: 10uF  [0805L]  (hidden comment: GRM21BR6YA106KE43L)
C97  ValueDisplayed: 10uF  [0805L]  (hidden comment: GRM21BR6YA106KE43L)
C98  ValueDisplayed: 0.1uF  [0603L]  (hidden comment: CGA3E2X7R1H104K080AA)
C99  ValueDisplayed: 33uF  [7343-31]  (hidden comment: T521D336M035ATE065)
C100  ValueDisplayed: 33uF  [7343-31]  (hidden comment: T521D336M035ATE065)
C101  ValueDisplayed: 33uF  VDC_V: 35V  [7343-31]  (hidden comment: T521D336M035ATE065)
C102  ValueDisplayed: 47uF  [CAPSMT_62_F61]  (hidden comment: Cap_Polarized)
C103  ValueDisplayed: 10uF  VDC_V: 35V  [0805L]  (hidden comment: GRM21BR6YA106KE43L)
C104  ValueDisplayed: 10uF  VDC_V: 35V  [0805L]  (hidden comment: GRM21BR6YA106KE43L)
C105  ValueDisplayed: 10uF  VDC_V: 35V  [0805L]  (hidden comment: GRM21BR6YA106KE43L)
C106  ValueDisplayed: 10uF  VDC_V: 35V  [0805L]  (hidden comment: GRM21BR6YA106KE43L)
C107  Cap_F: 10nF  VDC_V: 50V  [0603L]  (hidden comment: C0603C103J5RACTU)
C108  ValueDisplayed: 1000pF  VDC_V: 50V  [0402L]  (hidden comment: C1005NP01H102J050BA)
C109  ValueDisplayed: 330pF  [0603L]  (hidden comment: Capacitor)
C110  ValueDisplayed: 0.047uF  [0603L]  (hidden comment: Capacitor)
C111  ValueDisplayed: 10uF  [0805L]  (hidden comment: GRM21BR6YA106KE43L)
C112  ValueDisplayed: 10uF  [0805L]  (hidden comment: GRM21BR6YA106KE43L)
C113  ValueDisplayed: 1uF  [0603L]  (hidden comment: CGA3E1X7R1V105K080AC)
C114  ValueDisplayed: 0.047uF  [0603L]  (hidden comment: Capacitor)
C115  ValueDisplayed: 330pF  [0603L]  (hidden comment: Capacitor)
C116  ValueDisplayed: 150pF  [0603L]  (hidden comment: Capacitor)
C117  ValueDisplayed: 150pF  [0603L]  (hidden comment: Capacitor)
C118  ValueDisplayed: 0.01uF  [0603L]  (hidden comment: C0603C103J5RACTU)
C119  ValueDisplayed: 0.068uF  VDC_V: 50V  [0402L]  (hidden comment: CGA2B3X7R1H683K050BB)
C120  ValueDisplayed: 10uF  VDC_V: 35V  [0805L]  (hidden comment: GRM21BR6YA106KE43L)
C121  ValueDisplayed: 10uF  VDC_V: 35V  [0805L]  (hidden comment: GRM21BR6YA106KE43L)
C122  ValueDisplayed: 10uF  VDC_V: 35V  [0805L]  (hidden comment: GRM21BR6YA106KE43L)
C123  ValueDisplayed: 10uF  VDC_V: 35V  [0805L]  (hidden comment: GRM21BR6YA106KE43L)
C124  ValueDisplayed: 0.033uF  [0603L]  (hidden comment: GRM188R71H333KA61D)
C125  ValueDisplayed: 0.033uF  [0603L]  (hidden comment: GRM188R71H333KA61D)
C126  Cap_F: 18nF  VDC_V: 50V  [0603L]  (hidden comment: GRM188R71H183KA01D)
C127  Cap_F: 18nF  VDC_V: 50V  [0603L]  (hidden comment: GRM188R71H183KA01D)
C128  Cap_F: 470nF  VDC_V: 50V  [0805L]  (hidden comment: C2012X7R1H474K125AB)
C129  ValueDisplayed: 33pF  [0402L]  (hidden comment: Capacitor)
C130  ValueDisplayed: 2.2uF  [0603L]  (hidden comment: Capacitor)
C131  ValueDisplayed: 4700pF  [0402L]  (hidden comment: GRM155R71H472KA01D)
C132  ValueDisplayed: 680pF  [0402L]  (hidden comment: Capacitor)
C133  ValueDisplayed: 1uF  [0603L]  (hidden comment: CGA3E1X7R1V105K080AC)
C134  ValueDisplayed: 15pF  [0402L]  (hidden comment: Capacitor)
C135  ValueDisplayed: 33uF  VDC_V: 35V  [7343-31]  (hidden comment: T521D336M035ATE065)
C136  ValueDisplayed: 10uF  [1206_180]  (hidden comment: Capacitor)
C137  ValueDisplayed: 10uF  [1206_180]  (hidden comment: Capacitor)
C138  ValueDisplayed: 100pF  [0603L]  (hidden comment: Capacitor)
C140  ValueDisplayed: 100pF  [0603L]  (hidden comment: Capacitor)
D7  B220A-13-F  [SMA]  (value not drawn)
D8  150060VS75000  value Green  [WL-SMCW_GREEN]
J3  Receptacle_2x1  [On-Shore_ED120_2DS]  (value not drawn)
L3  Ind_H: 4.7µH  [FP-BMRHDY1010302R2MA1_SMT_IND_11MM2_10MM1-MFG]  (hidden comment: BMRHDY1010302R2MA1)
Q13  CSD17578Q3A  [DNH0008A]
Q14  CSD17578Q3A  [DNH0008A]
Q15  CSD17578Q3A  [DNH0008A]
Q16  CSD17578Q3A  [DNH0008A]
Q17  SISS27ADN-T1-GE3  [FP-SISS27ADN-T1-GE3_PowerPAK1212-8S-MFG]
Q19  NX3020NAKW,115  [SOT-323]
R47  ValueDisplayed: 0.005  [1206]  (hidden comment: WSLP12065L000FEA)
R48  ValueDisplayed: 0.005  [1206]  (hidden comment: WSLP12065L000FEA)
R49  ValueDisplayed: 0  [5106]  (hidden comment: 5106)
R50  ValueDisplayed: 4.99  [0603L]  (hidden comment: Resistor)
R51  ValueDisplayed: 56  [0603L]  (hidden comment: Resistor)
R52  ValueDisplayed: 10  [0603L]  (hidden comment: Resistor)
R53  ValueDisplayed: 10  [0603L]  (hidden comment: Resistor)
R54  ValueDisplayed: 4.99  [0603L]  (hidden comment: Resistor)
R55  ValueDisplayed: 56  [0603L]  (hidden comment: Resistor)
R56  ValueDisplayed: 1.0  [0805_HV]  (hidden comment: Resistor)
R57  ValueDisplayed: 15.0k  [0402L]  (hidden comment: CRCW040215K0FKED)
R58  ValueDisplayed: 40.2k  [0402L]  (hidden comment: Resistor)
R59  ValueDisplayed: 10  [0603L]  (hidden comment: CRCW060310R0JNEA)
R60  ValueDisplayed: 0  [2010]  (hidden comment: CRCW20100000Z0EF)
R61  ValueDisplayed: 33k  [0603L]  (hidden comment: CRCW060333K0JNEA)
R62  ValueDisplayed: 10.0k  [0603L]  (hidden comment: Resistor)
R63  ValueDisplayed: 10.0k  [0603L]  (hidden comment: Resistor)
R64  ValueDisplayed: 100k  [0603L]  (hidden comment: RC0603FR-07100KL)
R66  ValueDisplayed: 191k  [0603L]  (hidden comment: CRCW0603191KFKEA)
R67  ValueDisplayed: 100k  [0603L]  (hidden comment: CRCW0603100KFKEA)
R68  value 30.1k  [0603L]  (hidden comment: Resistor)
R70  ValueDisplayed: 220  [0603]  (hidden comment: RC0603FR-07220RL)
U10  BQ25731RSN  [RSN0032B-MFG]
VDDA_B  5010  [Keystone5010]  (value not drawn)

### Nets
3.3V: D8.2(A) R62.2 R63.2
GND: C87.2 C88.2 C89.2 C90.2 C91.2 C92.2 C93.2 C94.2(-) C95.2(-) C96.2 C97.2 C99.2(-) C100.2(-) C101.2(-) C102.2(-) C103.2 C104.2 C105.2 C106.2 C107.2 C108.2 C111.2 C112.2 C113.2 C116.2 C117.1 C120.2 C121.2 C122.2 C123.2 C124.2 C125.2 C126.2 C127.2 C128.2 C129.1 C130.2 C131.1 C132.2 C133.2 C134.2 C135.2(-) C136.2 C137.2 C138.2 C140.2 D7.2(A) J3.1 Q14.1(S) Q14.2(S) Q14.3(S) Q15.1(S) Q15.2(S) Q15.3(S) Q19.2(S) R51.1 R55.1 R64.1 R66.1 R67.1 R68.2 U10.5(OTG/VAP) U10.14(CMPIN) U10.27(GND) U10.33(Thermal_Pad)
REGN_B: C130.1 R59.1 U10.28(REGN)
VBAT_B: C98.1 C113.1 Q17.5-6-7-8(D) R47.1 R49.2 R52.2
VBUS_B: C128.1 R56.1 U10.1(VBUS)
VDDA_B: C133.1 R59.2 R61.2 U10.7(VDDA) VDDA_B.1
VIN_PROT: C99.1(+) C100.1(+) C103.1 C104.1 C105.1 C106.1 C120.1 C121.1 C122.1 C123.1 R48.1 R50.2 R56.2  [project net IN_ISNS_N]
ACN_B: C118.2 C125.1 R54.1 U10.2(ACN)
ACP_B: C118.1 C124.1 R50.1 U10.3(ACP)
CHG_B_SCL: U10.13(SCL)
CHG_B_SDA: U10.12(SDA)
CHG_OK_B: Q19.1(G) R63.1 U10.4(CHRG_OK)
IADPT_B: C138.1 R66.2 U10.8(IADPT)
IBAT_B: C140.1 R67.2 U10.9(IBAT)
ILIM: U10.6(ILIM_HIZ)
PROCHOT_B: R62.1 U10.11(~{PROCHOT})
PSYS_B: R68.1 U10.10(PSYS)
SRN_B: C119.2 C127.1 R53.1 U10.19(SRN)
SRP_B: C119.1 C126.1 R52.1 U10.20(SRP)
NetBAT_B_1: BAT_B.1 J3.2 R60.2
NetC87_1: C87.1 C88.1 C89.1 C90.1 C91.1 C92.1 C93.1 C94.1(+) C95.1(+) C96.1 C97.1 C101.1(+) C102.1(+) C111.1 C112.1 Q16.5(D) Q16.6(D) Q16.7(D) Q16.8(D) Q16.9(D) Q17.1(S) Q17.2(S) Q17.3(S) R49.1 U10.22(VSYS)
NetC98_2: C98.2 C135.1(+) C136.1 C137.1 D7.1(K) R47.2 R53.2 R60.1
NetC107_1: C107.1 C108.1 Q13.5(D) Q13.6(D) Q13.7(D) Q13.8(D) Q13.9(D) R48.2 R54.2
NetC109_1: C109.1 C114.2 L3.1 Q13.1(S) Q13.2(S) Q13.3(S) Q14.5(D) Q14.6(D) Q14.7(D) Q14.8(D) Q14.9(D) U10.32(SW1)
NetC109_2: C109.2 R51.2
NetC110_1: C110.1 U10.25(BTST2)
NetC110_2: C110.2 C115.1 L3.2 Q15.5(D) Q15.6(D) Q15.7(D) Q15.8(D) Q15.9(D) Q16.1(S) Q16.2(S) Q16.3(S) U10.23(SW2)
NetC114_1: C114.1 U10.30(BTST1)
NetC115_2: C115.2 R55.2
NetC116_1: C116.1 Q14.4(G) U10.29(LODRV1)
NetC117_2: C117.2 Q15.4(G) U10.26(LODRV2)
NetC129_2: C129.2 R58.2 U10.16(COMP1)
NetC131_2: C131.2 R58.1
NetC132_1: C132.1 R57.2
NetC134_1: C134.1 R57.1 U10.17(COMP2)
NetD8_1: D8.1(K) R70.2
NetQ13_4: Q13.4(G) U10.31(HIDRV1)
NetQ16_4: Q16.4(G) U10.24(HIDRV2)
NetQ17_4: Q17.4(G) U10.21(~{BATDRV})
NetQ19_3: Q19.3(D) R70.1
NetR61_1: R61.1 R64.2 U10.18(CELL_BATPRESZ)

Not connected (* = marked no-connect by the designer): U10 15(CMPOUT)*

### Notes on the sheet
- BATB Screw Terminal
- (near J3) 16.8V MAX
- (near J3) 4A MAX
- 4 CELL

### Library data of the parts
BAT_B VDDA_B = CMP-0055147-1: as BAT_A on sheet BQ25731_A
C87 = CMP-0006850-4: as C33 on sheet BQ25731_A
C88-C93 C96 C97 C111 C112 = CMP-0008310-2: as C34-C39 on sheet BQ25731_A
C94 C95 C101 C135 = CMP-0011849-2: as C40 on sheet BQ25731_A
C98 = CMP-0007078-4: as C44 on sheet BQ25731_A
C99 C100 = CMP-0011849-2: as C45 on sheet BQ25731_A
C102 = CMP-0012121-3: as C48 on sheet BQ25731_A
C103-C106 C120-C123 = CMP-0008310-2: as C49 on sheet BQ25731_A
C107 = CMP-0006850-4: as C53 on sheet BQ25731_A
C108 = CMP-0006254-2: as C54 on sheet BQ25731_A
C109 C115 = CMP-0007449-4: as C55 on sheet BQ25731_A
C110 C114 = CMP-0007423-4: as C56 on sheet BQ25731_A
C113 C133 = CMP-0007067-4: as C59 on sheet BQ25731_A
C116 C117 = CMP-0006880-4: as C62 on sheet BQ25731_A
C118 = CMP-0006850-4: as C64 on sheet BQ25731_A
C119 = CMP-0006331-2: as C65 on sheet BQ25731_A
C124 C125 = CMP-0007451-4: as C70 on sheet BQ25731_A
C126 C127 = CMP-0007440-5: as C72 on sheet BQ25731_A
C128 = CMP-0007880-2: as C74 on sheet BQ25731_A
C129 = CMP-0006454-2: as C75 on sheet BQ25731_A
C130 = CMP-0007356-5: as C76 on sheet BQ25731_A
C131 = CMP-0006692-2: as C77 on sheet BQ25731_A
C132 = CMP-0006486-2: as C78 on sheet BQ25731_A
C134 = CMP-0006420-2: as C80 on sheet BQ25731_A
C136 C137 = CMP-0008965-2: as C82 on sheet BQ25731_A
C138 C140 = CMP-0006840-4: as C84 on sheet BQ25731_A
D7 = CMP-0028399-2: as D5 on sheet BQ25731_A
D8 = CMP-0002894-2: as D6 on sheet BQ25731_A
J3 = CMP-0074910-1: as J2 on sheet BQ25731_A
L3 = CMP-0088941-1: as L2 on sheet BQ25731_A
Q13-Q16 = CMP-0000591-2: as Q6-Q9 on sheet BQ25731_A
Q17 = CMP-0092727-1: as Q10 on sheet BQ25731_A
Q19 = CMP-0000643-2: as Q12 on sheet BQ25731_A
R47 R48 = CMP-0084411-1: as R23 on sheet BQ25731_A
R49 = CMP-0020833-2: as R25 on sheet BQ25731_A
R50 R54 = CMP-0022478-4: as R26 on sheet BQ25731_A
R51 R55 = CMP-0025829-4: as R27 on sheet BQ25731_A
R52 R53 = CMP-0025703-4: as R28 on sheet BQ25731_A
R56 = CMP-0020487-3: as R32 on sheet BQ25731_A
R57 = CMP-0026027-3: as R33 on sheet BQ25731_A
R58 = CMP-0026367-2: as R34 on sheet BQ25731_A
R59 = CMP-0025703-4: as R35 on sheet BQ25731_A
R60 = CMP-0016044-3: as R36 on sheet BQ25731_A
R61 = CMP-0025786-4: as R37 on sheet BQ25731_A
R62 R63 = CMP-0021998-4: as R38 on sheet BQ25731_A
R64 = CMP-0022735-5: as R40 on sheet BQ25731_A
R66 = CMP-0022101-4: as R42 on sheet BQ25731_A
R67 = CMP-0021990-4: as R43 on sheet BQ25731_A
R68 = CMP-0022324-4: as R44 on sheet BQ25731_A
R70 = CMP-0022918-5: as R46 on sheet BQ25731_A
U10 = CMP-0089013-3: as U9 on sheet BQ25731_A

## Sheet Sensing.SchDoc
size 431 x 279 mm; Date: Not shown in title block; ApprovedBy: Not shown in title block; CheckedBy: Not shown in title block; Author: Not shown in title block; CompanyName: Not shown in title block; Engineer: Not shown in title block; Organization: Not shown in title block; Address1: Not shown in title block; Address2: Not shown in title block; Address3: Not shown in title block; Address4: Not shown in title block; DocumentNumber: 1; Revision: Use project parameter SCH_Rev; SheetNumber: 1; SheetTotal: 1; PageSetup: Record=PageOptions¦CenterHorizontal=True¦CenterVertical=True¦PrintScale=1.00¦XCorrection=1.00¦YCorrection=1.00¦PrintKind=0¦BorderSize=5000000¦LeftOffset=0¦BottomOffset=0¦Orientation=2¦PaperLength=1000¦PaperWidth=1000¦Scale=100¦PaperSource=15¦PrintQuality=600¦MediaType=1¦DitherType=10¦PaperKind=Letter¦PrintScaleMode=1
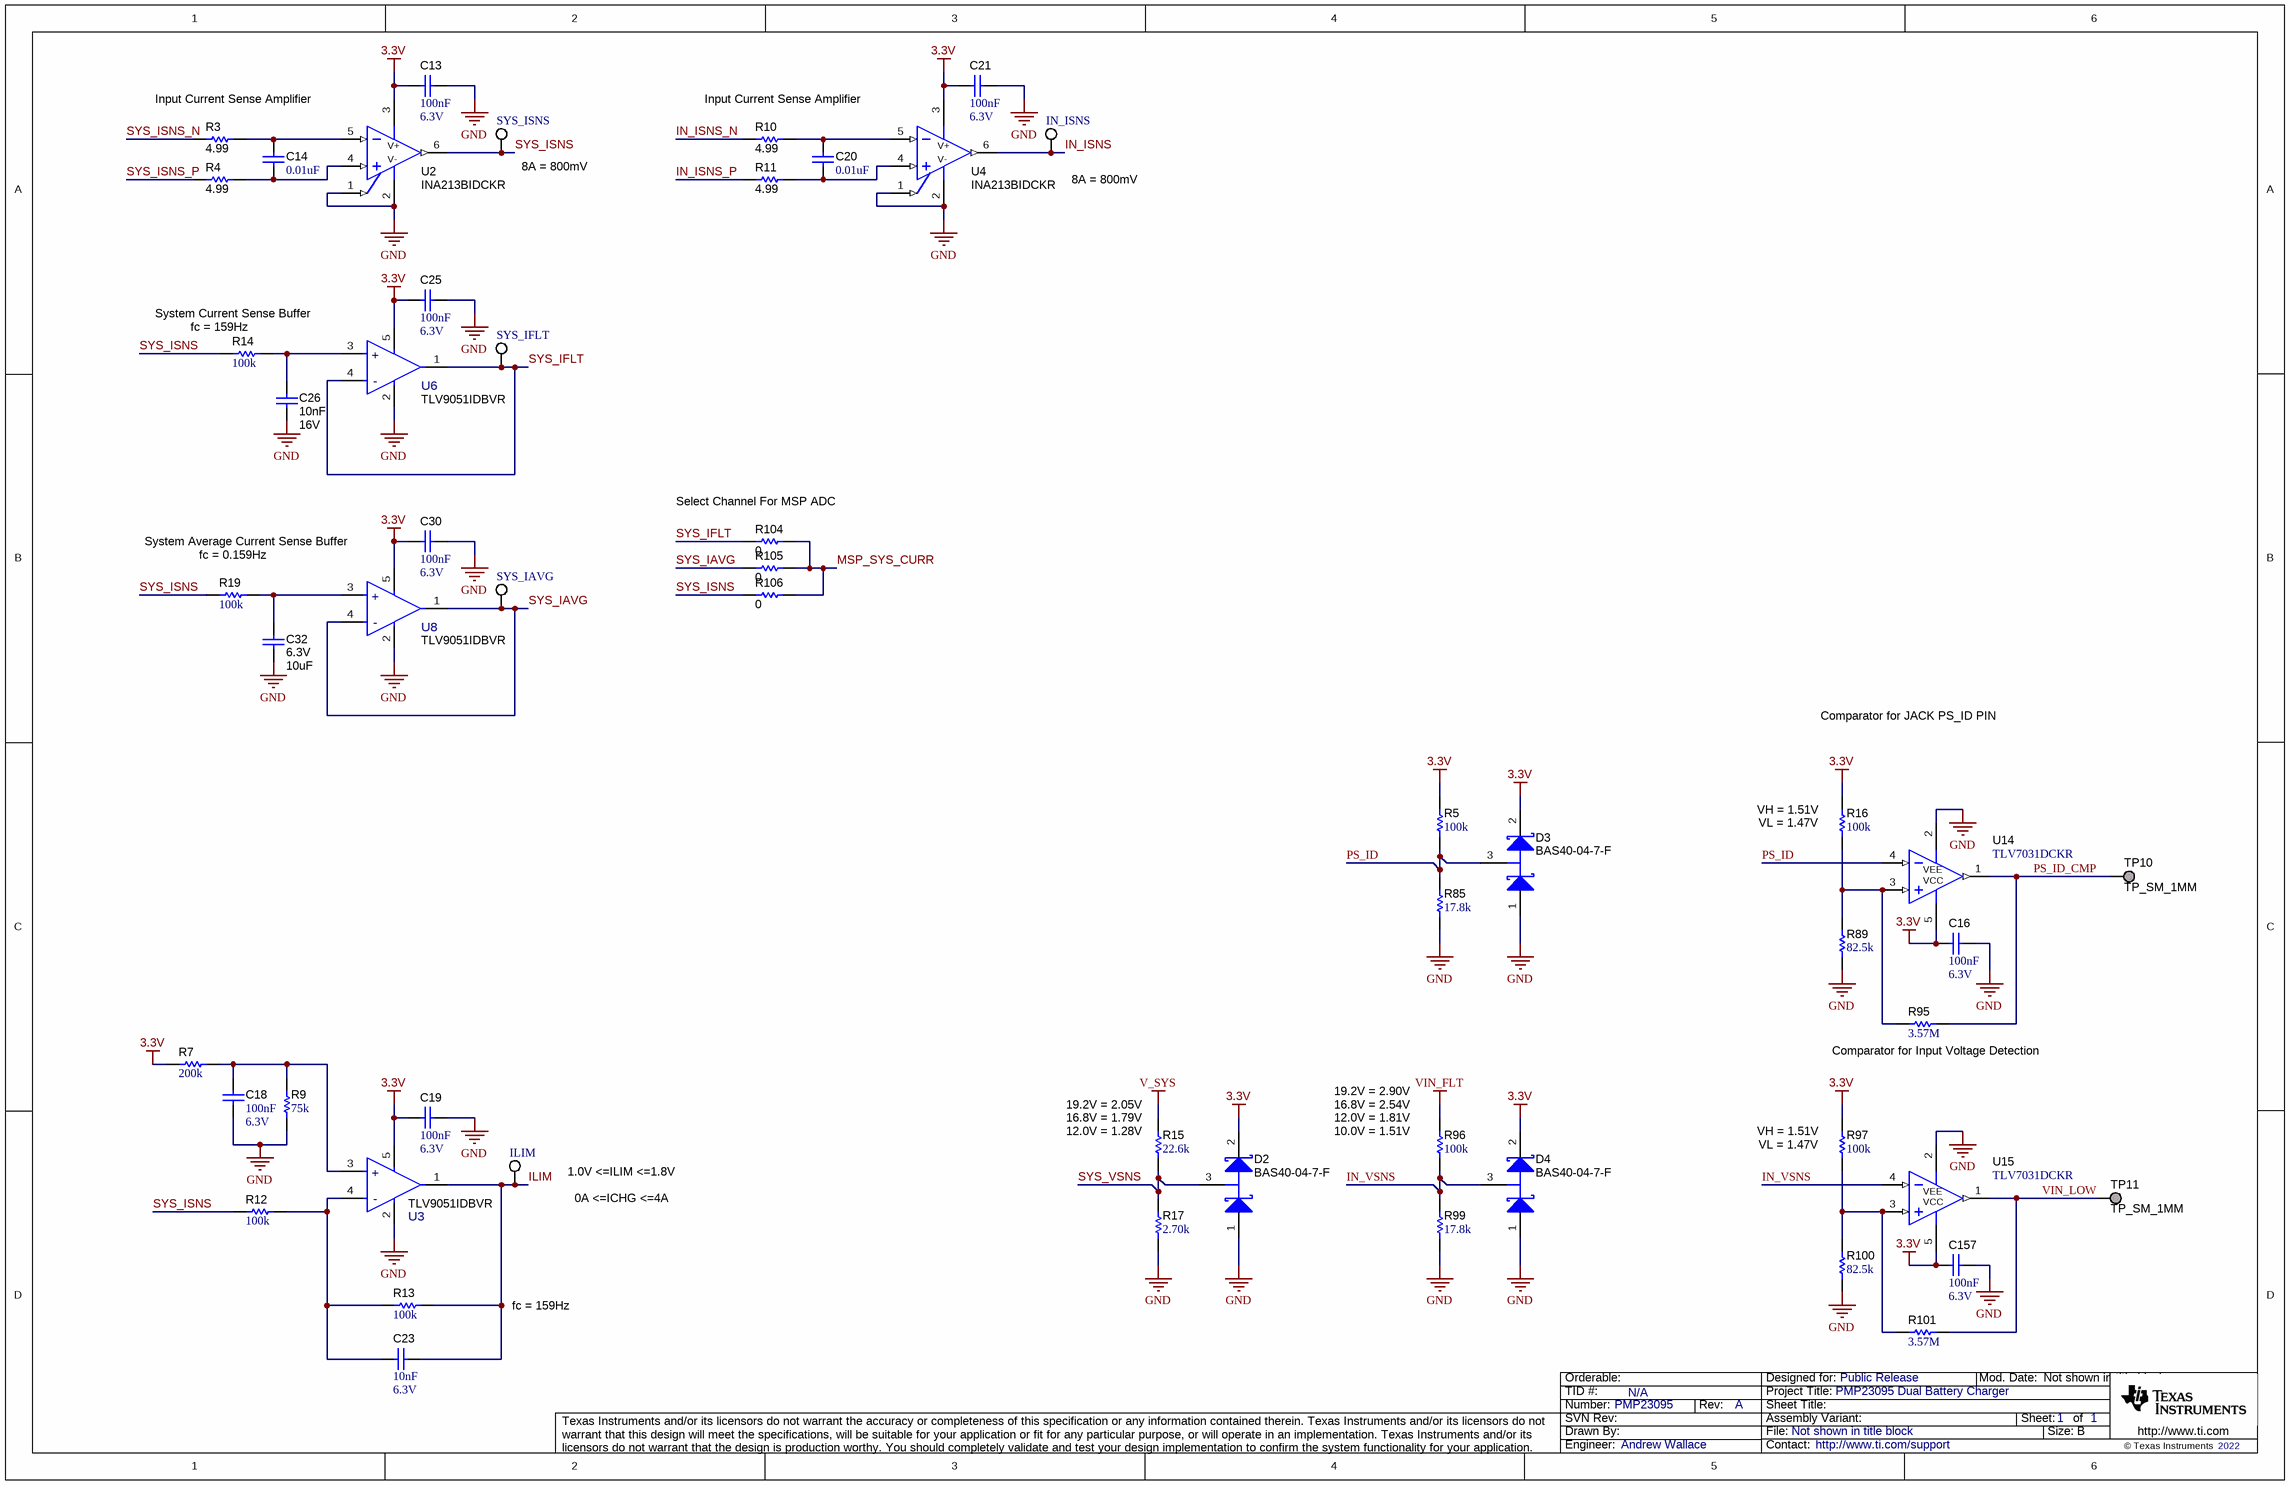
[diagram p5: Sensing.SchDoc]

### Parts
C13  Cap_F: 100nF  VDC_V: 6.3V  [0603]  (hidden comment: C0603C104K9RAC7867)
C14  ValueDisplayed: 0.01uF  [0603L]  (hidden comment: C0603C103J5RACTU)
C16  Cap_F: 100nF  VDC_V: 6.3V  [0603]  (hidden comment: C0603C104K9RAC7867)
C18  Cap_F: 100nF  VDC_V: 6.3V  [0603]  (hidden comment: C0603C104K9RAC7867)
C19  Cap_F: 100nF  VDC_V: 6.3V  [0603]  (hidden comment: C0603C104K9RAC7867)
C20  ValueDisplayed: 0.01uF  [0603L]  (hidden comment: C0603C103J5RACTU)
C21  Cap_F: 100nF  VDC_V: 6.3V  [0603]  (hidden comment: C0603C104K9RAC7867)
C23  Cap_F: 10nF  VDC_V: 6.3V  [0402]  (hidden comment: GRM155R70J103KA01D)
C25  Cap_F: 100nF  VDC_V: 6.3V  [0603]  (hidden comment: C0603C104K9RAC7867)
C26  Cap_F: 10nF  VDC_V: 16V  [0603]  (hidden comment: C0603C103K4RACTU)
C30  Cap_F: 100nF  VDC_V: 6.3V  [0603]  (hidden comment: C0603C104K9RAC7867)
C32  VDC_V: 6.3V  ValueDisplayed: 10uF  [0603]  (hidden comment: GRM188R60J106ME84)
C157  Cap_F: 100nF  VDC_V: 6.3V  [0603]  (hidden comment: C0603C104K9RAC7867)
D2  BAS40-04-7-F  [SOT-23L]
D3  BAS40-04-7-F  [SOT-23L]
D4  BAS40-04-7-F  [SOT-23L]
ILIM  5012  [Keystone5012]  (value not drawn)
IN_ISNS  5012  [Keystone5012]  (value not drawn)
R3  ValueDisplayed: 4.99  [0603L]  (hidden comment: Resistor)
R4  ValueDisplayed: 4.99  [0603L]  (hidden comment: Resistor)
R5  ValueDisplayed: 100k  [0603]  (hidden comment: RC0603FR-07100KL)
R7  ValueDisplayed: 200k  [0603]  (hidden comment: RC0603FR-07280KL)
R9  ValueDisplayed: 75k  [0603]  (hidden comment: RC0603FR-07100KL)
R10  ValueDisplayed: 4.99  [0603L]  (hidden comment: Resistor)
R11  ValueDisplayed: 4.99  [0603L]  (hidden comment: Resistor)
R12  ValueDisplayed: 100k  [0603]  (hidden comment: RC0603FR-07100KL)
R13  ValueDisplayed: 100k  [0603]  (hidden comment: RC0603FR-07100KL)
R14  ValueDisplayed: 100k  [0603]  (hidden comment: RC0603FR-07100KL)
R15  ValueDisplayed: 22.6k  [0603]  (hidden comment: RC0603FR-0722K6L)
R16  ValueDisplayed: 100k  [0603]  (hidden comment: RC0603FR-07100KL)
R17  ValueDisplayed: 2.70k  [0603]  (hidden comment: RC0603FR-072K7L)
R19  ValueDisplayed: 100k  [0603]  (hidden comment: RC0603FR-07100KL)
R85  ValueDisplayed: 17.8k  [0603]  (hidden comment: CRCW060317K8FKEA)
R89  ValueDisplayed: 82.5k  [0603]  (hidden comment: RC0603FR-0782K5L)
R95  ValueDisplayed: 3.57M  [0603]  (hidden comment: CRCW06033M57FKEA)
R96  ValueDisplayed: 100k  [0603]  (hidden comment: RC0603FR-07100KL)
R97  ValueDisplayed: 100k  [0603]  (hidden comment: RC0603FR-07100KL)
R99  ValueDisplayed: 17.8k  [0603]  (hidden comment: CRCW060317K8FKEA)
R100  ValueDisplayed: 82.5k  [0603]  (hidden comment: RC0603FR-0782K5L)
R101  ValueDisplayed: 3.57M  [0603]  (hidden comment: CRCW06033M57FKEA)
R104  ValueDisplayed: 0  [0603]  (hidden comment: RMCF0603ZT0R00)
R105  ValueDisplayed: 0  [0603]  (hidden comment: RMCF0603ZT0R00)
R106  ValueDisplayed: 0  [0603]  (hidden comment: RMCF0603ZT0R00)
SYS_IAVG  5012  [Keystone5012]  (value not drawn)
SYS_IFLT  5012  [Keystone5012]  (value not drawn)
SYS_ISNS  5012  [Keystone5012]  (value not drawn)
TP10  TP_SM_1MM  [TP_SM_1MM]  (no BOM)
TP11  TP_SM_1MM  [TP_SM_1MM]  (no BOM)
U2  INA213BIDCKR  [DCK0006A_N]
U3  TLV9051IDBVR  [DBV0005A-MFG]
U4  INA213BIDCKR  [DCK0006A_N]
U6  TLV9051IDBVR  [DBV0005A-MFG]
U8  TLV9051IDBVR  [DBV0005A-MFG]
U14  TLV7031DCKR  [DCK0005A_N]
U15  TLV7031DCKR  [DCK0005A_N]

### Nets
3.3V: C13.1 C16.1 C19.1 C21.1 C25.1 C30.1 C157.1 D2.2(K) D3.2(K) D4.2(K) R5.2 R7.1 R16.2 R97.2 U2.3(V+) U3.5(V+) U4.3(V+) U6.5(V+) U8.5(V+) U14.5(VCC) U15.5(VCC)
GND: C13.2 C16.2 C18.2 C19.2 C21.2 C25.2 C26.2 C30.2 C32.2 C157.2 D2.1(A) D3.1(A) D4.1(A) R9.1 R17.1 R85.1 R89.1 R99.1 R100.1 U2.1(REF) U2.2(GND) U3.2(V-) U4.1(REF) U4.2(GND) U6.2(V-) U8.2(V-) U14.2(VEE) U15.2(VEE)
IN_ISNS_N: R10.2
SYS_ISNS_N: R3.2 R15.2  [also labelled V_SYS]
SYS_ISNS_P: R4.2
VIN_FLT: R96.2
ILIM: C23.2 ILIM.1 R13.2 U3.1(OUT)
IN_ISNS: IN_ISNS.1 U4.6(OUT)
IN_ISNS_P: R11.1
IN_VSNS: D4.3(C) R96.1 R99.2 U15.4(IN-)
MSP_SYS_CURR: R104.2 R105.2 R106.2
PS_ID: D3.3(C) R5.1 R85.2 U14.4(IN-)
PS_ID_CMP: R95.2 TP10.1 U14.1(OUT)
SYS_IAVG: R105.1 SYS_IAVG.1 U8.1(OUT) U8.4(IN-)
SYS_IFLT: R104.1 SYS_IFLT.1 U6.1(OUT) U6.4(IN-)
SYS_ISNS: R12.1 R14.1 R19.1 R106.1 SYS_ISNS.1 U2.6(OUT)
SYS_VSNS: D2.3(C) R15.1 R17.2
VIN_LOW: R101.2 TP11.1 U15.1(OUT)
NetC14_1: C14.1 R4.1 U2.4(IN+)
NetC14_2: C14.2 R3.1 U2.5(IN-)
NetC18_1: C18.1 R7.2 R9.2 U3.3(IN+)
NetC20_1: C20.1 R11.2 U4.4(IN+)
NetC20_2: C20.2 R10.1 U4.5(IN-)
NetC23_1: C23.1 R12.2 R13.1 U3.4(IN-)
NetC26_1: C26.1 R14.2 U6.3(IN+)
NetC32_1: C32.1 R19.2 U8.3(IN+)
NetR16_1: R16.1 R89.2 R95.1 U14.3(IN+)
NetR97_1: R97.1 R100.2 R101.1 U15.3(IN+)

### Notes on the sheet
- Input Current Sense Amplifier
- (near SYS_ISNS) 8A = 800mV
- (near IN_ISNS) 8A = 800mV
- (near R14) fc = 159Hz
- (near R14) System Current Sense Buffer
- (near R104) Select Channel For MSP ADC
- (near R19) fc = 0.159Hz
- System Average Current Sense Buffer
- Comparator for JACK PS_ID PIN
- (near R16) VH = 1.51V
- (near R16) VL = 1.47V
- (near R15) 19.2V = 2.05V
- (near R96) 19.2V = 2.90V
- (near R96) 16.8V = 2.54V
- (near R95) Comparator for Input Voltage Detection
- (near ILIM) 1.0V <=ILIM <=1.8V
- (near R15) 16.8V = 1.79V
- (near R15) 12.0V = 1.28V
- (near R96) 12.0V = 1.81V
- (near R96) 10.0V = 1.51V
- (near R97) VH = 1.51V
- (near R97) VL = 1.47V
- 0A <=ICHG <=4A
- fc = 159Hz

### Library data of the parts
C13 C16 C18 C19 C21 C25 C30 C157 = CMP-0086271-1: CAP, CERM, 0.1 µF, 6.3 V,+/- 10%, X7R, 0603; Manufacturer: Kemet; TaMin_C: -55°C; Polarized: N; SizeAreaWB_mm2: 4.68; U/M: EA; Value: 0.1uF; TaMax_C: 125°C; SizeZ_mm: 1; SizeX_mm: 1.6; SizeY_mm: 0.8; SizeArea_mm2: 1.28; AEC Category: Q200; ValueDisplayed: 0.1µF
C14 C20 = CMP-0006850-4: as C64 on sheet BQ25731_A
C23 = CMP-0006622-2: CAP, CERM, 0.01 uF, 6.3 V, +/- 10%, X7R, 0402; Manufacturer: MuRata; TaMin_C: -55°C; Polarized: N; SizeAreaWB_mm2: 3; Value1: Unknown; U/M: EA; Value: 0.01uF; TaMax_C: 125°C; SizeZ_mm: 0.6; SizeX_mm: 1; SizeY_mm: 0.5; AEC Category: Q200
C26 = CMP-0006853-4: CAP, CERM, 0.01 uF, 16 V, +/- 10%, X7R, 0603; Manufacturer: Kemet; TaMin_C: -55°C; Polarized: N; SizeAreaWB_mm2: 4.68; Value1: Unknown; U/M: EA; Value: 0.01uF; TaMax_C: 125°C; SizeZ_mm: 1; SizeX_mm: 1.6; SizeY_mm: 0.8; SizeArea_mm2: 1.28; AEC Category: Q200
C32 = CMP-0007304-5: CAP, CERM, 10 uF, 6.3 V, +/- 20%, X5R, 0603; Manufacturer: MuRata; TaMin_C: -55°C; Polarized: N; SizeAreaWB_mm2: 4.68; Value1: Unknown; U/M: EA; Value: 10uF; TaMax_C: 85°C; SizeZ_mm: 1; SizeX_mm: 1.6; SizeY_mm: 0.8; SizeArea_mm2: 1.28; Cap_F: 10µF; AEC Category: Q200
D2-D4 = CMP-0076970-2: Diode, Schottky, 40 V, 0.2 A, SOT-23; Manufacturer: Diodes Inc.; SizeAreaWB_mm2: 14.0; Vr_V: 40V; SizeArea_mm2: 7.5; TJmax_C: 125°C; AEC Category: Q101; Value: 40V; SizeZ_mm: 1.1; Green_REACh: Incomplete; Io_A: 200mA; Vf_V: 1V; SizeY_mm: 3.0; Green_Lifecycle: Not Set; Value1: 0.2A; SizeX_mm: 2.5
ILIM IN_ISNS SYS_IAVG SYS_IFLT SYS_ISNS = CMP-0055149-1: Test Point, Multipurpose, White, TH; Manufacturer: Keystone; CNHeader: FALSE; Green_Lifecycle: Active; Green_REACh: Passed; CT: TRUE; ContactFinish: Silver
R3 R4 R10 R11 = CMP-0022478-4: as R26 on sheet BQ25731_A
R5 R12-R14 R16 R19 R96 R97 = CMP-0022735-5: RES, 100 k, 1%, 0.1 W, 0603; Manufacturer: Yageo; Power_W: 100mW; TempCo: 100 ppm/C; Value: 100k; EIA_Code: E96; SizeX_mm: 1.6; SizeY_mm: 0.8; SizeZ_mm: 1; Value2: 0.1W; SizeArea_mm2: 1.28; AEC Qualified: N; VDC_V: 75V; AEC Category: Q200; SizeAreaWB_mm2: 4.68
R7 = CMP-0022969-4: RES, 280 k, 1%, 0.1 W, 0603; Manufacturer: Yageo; Power_W: 100mW; TempCo: 100 ppm/C; Value_Code: 280k; Value: 280k; EIA_Code: E96; SizeX_mm: 1.6; SizeY_mm: 0.8; SizeZ_mm: 1; Value2: 0.1W; SizeArea_mm2: 1.28; AEC Qualified: N; VDC_V: 75V; AEC Category: Q200; SizeAreaWB_mm2: 4.68
R9 = CMP-0022735-5: RES, 100 k, 1%, 0.1 W, 0603; Manufacturer: Yageo; Power_W: 100mW; TempCo: 100 ppm/C; Value_Code: 100k; Value: 100k; EIA_Code: E96; SizeX_mm: 1.6; SizeY_mm: 0.8; SizeZ_mm: 1; Value2: 0.1W; SizeArea_mm2: 1.28; AEC Qualified: N; VDC_V: 75V; AEC Category: Q200; SizeAreaWB_mm2: 4.68
R15 = CMP-0022924-5: RES, 22.6 k, 1%, 0.1 W, 0603; Manufacturer: Yageo; Power_W: 100mW; TempCo: 100 ppm/C; Value_Code: 22k6; Value: 22.6k; EIA_Code: E96; SizeX_mm: 1.6; SizeY_mm: 0.8; SizeZ_mm: 1; Value2: 0.1W; SizeArea_mm2: 1.28; AEC Qualified: N; VDC_V: 75V; AEC Category: Q200; SizeAreaWB_mm2: 4.68
R17 = CMP-0022996-5: RES, 2.70 k, 1%, 0.1 W, 0603; Manufacturer: Yageo; Power_W: 100mW; TempCo: 100 ppm/C; Value_Code: 2k70; Value: 2.70k; Res_ohm: 2.7k; SizeX_mm: 1.6; SizeY_mm: 0.8; SizeZ_mm: 1; Value2: 0.1W; SizeArea_mm2: 1.28; AEC Qualified: N; VDC_V: 75V; AEC Category: Q200; SizeAreaWB_mm2: 4.68
R85 R99 = CMP-0022090-2: RES, 17.8 k, 1%, 0.1 W, 0603; Manufacturer: Vishay-Dale; Power_W: 100mW; TempCo: 100 ppm/C; Value_Code: 17k8; U/M: EA; Value: 17.8k; EIA_Code: E96; SizeX_mm: 1.6; SizeY_mm: 0.8; SizeZ_mm: 1; Value2: 0.1W; SizeArea_mm2: 1.28; VDC_V: 75V; AEC Category: Q200
R89 R100 = CMP-0023291-5: RES, 82.5 k, 1%, 0.1 W, 0603; Manufacturer: Yageo; Power_W: 100mW; TempCo: 100 ppm/C; Value_Code: 82k5; Value: 82.5k; EIA_Code: E96; SizeX_mm: 1.6; SizeY_mm: 0.8; SizeZ_mm: 1; Value2: 0.1W; SizeArea_mm2: 1.28; AEC Qualified: N; VDC_V: 75V; AEC Category: Q200; SizeAreaWB_mm2: 4.68
R95 R101 = CMP-0022391-4: RES, 3.57 M, 1%, 0.1 W, AEC-Q200 Grade 0, 0603; Manufacturer: Vishay-Dale; Power_W: 100mW; TempCo: 100 ppm/C; Value_Code: 3M57; Value: 3.57Meg; EIA_Code: E96; SizeX_mm: 1.6; SizeY_mm: 0.8; SizeZ_mm: 1; Value2: 0.1W; SizeArea_mm2: 1.28; AEC Qualified: Y; VDC_V: 75V; AEC Category: Q200; AEC Grade: 0
R104-R106 = CMP-0023343-3: RES, 0, 1%, 0.1 W, AEC-Q200 Grade 0, 0603; Manufacturer: Stackpole Electronics Inc; Power_W: 100mW; TempCo: ppm/C; U/M: EA; Value: 0; SizeX_mm: 1.6; SizeY_mm: 0.8; SizeZ_mm: 1; Value2: 0.1W; SizeArea_mm2: 1.28; AEC Qualified: Y; AEC Category: Q200
TP10 TP11 = CMP-0003825-1: 1mm Test Point, SMT; Manufacturer: Any
U2 U4 = CMP-0077336-3: 26-V, Bi-Directional, Zero-Drift, High Accuracy, Low-/High-Side, Voltage Out Current Shunt Monitor, DCK0006A (SOT-SC70-6); Manufacturer: Texas Instruments; Alternate PartNumber: INA213BIDCKT; CompType: IC; SizeAreaWB_mm2: 9.3; SizeArea_mm2: 4.2; Rating: Catalog; SizeY_mm: 2.0; AEC Category: Q200; SizeZ_mm: 1.1; SizeX_mm: 2.1; AEC Qualified: N
U3 U6 U8 = CMP-0090312-1: General Purpose Amplifier 1 Circuit Rail-to-Rail SOT-23-5; Manufacturer: Texas Instruments; Output Current Per Channel: 50mA; Gain Bandwidth: 5MHz; Nominal Supply Current: 330uA; Min Supply Voltage: 1.8V; Standoff Height: 0mm; TJmax_C: +150°C; Input Offset Voltage: 0.33mV; Number Of Channels: 1; AEC Qualified: No; Max Supply Voltage: 5.5V; SizeZ_mm: 1.45mm; Input Bias Current: 0.000002uA; Voltage Gain: 104dB; TaMin_C: -40°C
U14 U15 = CMP-0860137-1: Small-Size Nanopower Low-Voltage Comparator, DCK0005A (SOT-SC70-5); Manufacturer: Texas Instruments; Alternate PartNumber: TLV7031DCKT; CompType: IC; SizeAreaWB_mm2: 9.3; SizeX_mm: 2.1; SizeArea_mm2: 4.2; AEC Category: Q200; SizeY_mm: 2; Rating: Catalog; AEC Qualified: N; SizeZ_mm: 1.1

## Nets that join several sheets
3.3V: MSP (29 pins), BQ25731_A (D6.2 R38.2 R39.2), BQ25731_B (D8.2 R62.2 R63.2), Sensing (21 pins)
GND: InputProtection (32 pins), MSP (39 pins), BQ25731_A (66 pins), BQ25731_B (65 pins), Sensing (28 pins)
IN_ISNS_N: InputProtection (8 pins), MSP (J8.1), BQ25731_A (13 pins), BQ25731_B (13 pins), Sensing (R10.2)
SYS_ISNS_N: InputProtection (12 pins), MSP (J8.3), Sensing (R3.2 R15.2)
SYS_ISNS_P: InputProtection (14 pins), Sensing (R4.2)
VBAT_A: InputProtection (6 pins), BQ25731_A (6 pins)
VBAT_B: InputProtection (8 pins), BQ25731_B (6 pins)
VIN_FLT: InputProtection (11 pins), Sensing (R96.2)
CHG_A_SCL: MSP (J6.3 R75.1 U12.3), BQ25731_A (U9.13)
CHG_A_SDA: MSP (J6.5 R76.1 U12.2), BQ25731_A (U9.12)
CHG_B_SCL: MSP (J6.9 R77.1 U12.5), BQ25731_B (U10.13)
CHG_B_SDA: MSP (J6.7 R78.1 U12.4), BQ25731_B (U10.12)
ILIM: BQ25731_A (U9.6), BQ25731_B (U10.6), Sensing (C23.2 ILIM.1 R13.2 U3.1)
IN_ISNS: MSP (U11.8), Sensing (IN_ISNS.1 U4.6)
IN_ISNS_P: InputProtection (9 pins), Sensing (R11.1)
MSP_SYS_CURR: MSP (U11.7), Sensing (R104.2 R105.2 R106.2)
PS_ID: InputProtection (J12.1), Sensing (D3.3 R5.1 R85.2 U14.4)
PS_ID_CMP: MSP (U11.3), Sensing (R95.2 TP10.1 U14.1)
VIN_LOW: MSP (U11.4), Sensing (R101.2 TP11.1 U15.1)

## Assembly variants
001: not fitted C17 C40 C42 C43 C46 C47 C48 C57 C58 C65 C69 C72 C73 C85 C94 C96 C97 C100 C101 C102 C111 C112 C119 C123 C126 C127 C139 C141 C154 C155 C156 D5 D7 Q10 Q17 R5 R20 R21 R41 R43 R67 R85 R97 R100 R? R? R? R? R? R? R?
